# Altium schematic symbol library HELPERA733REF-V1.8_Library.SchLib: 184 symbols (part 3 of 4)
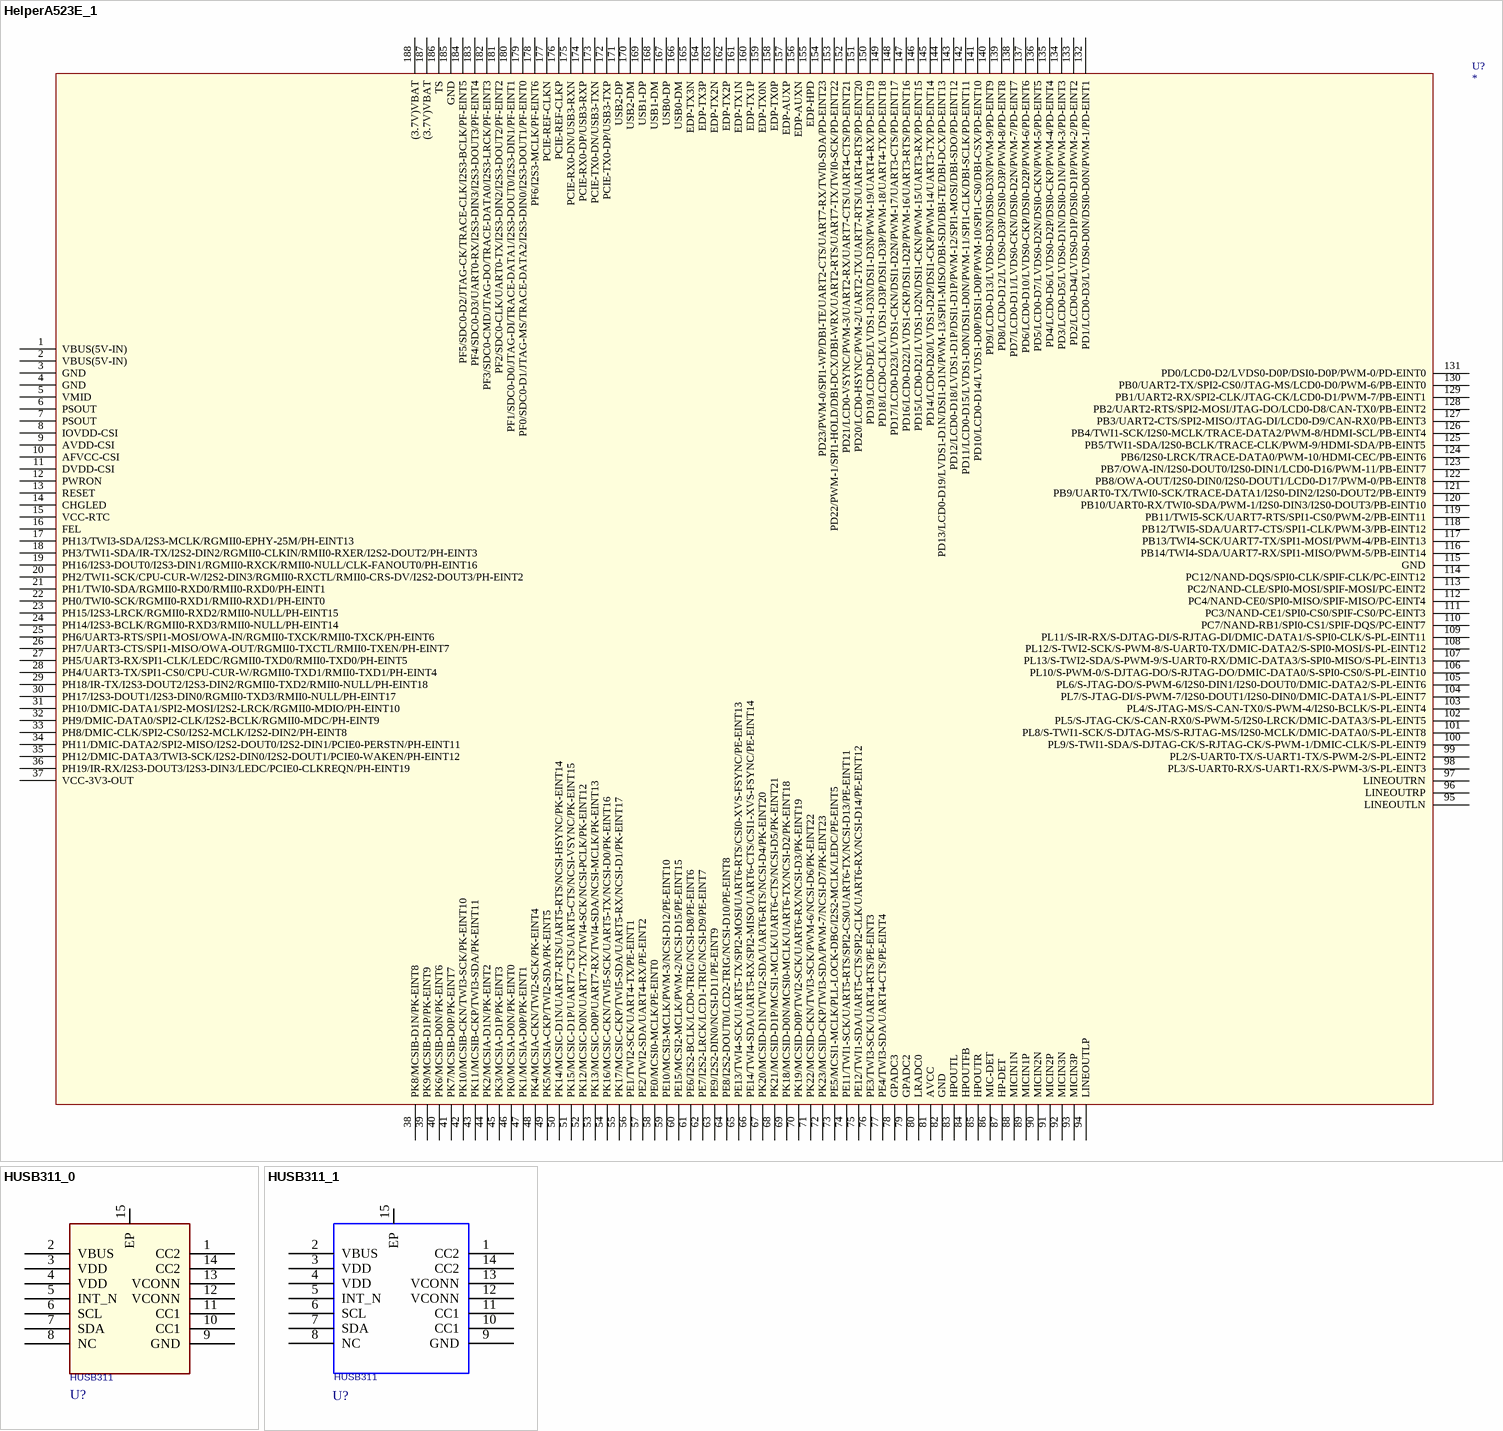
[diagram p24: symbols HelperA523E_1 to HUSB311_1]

## HelperA523E_1
designator U?
pins: 1 VBUS(5V-IN), 2 VBUS(5V-IN), 3 GND, 4 GND, 5 VMID, 6 PSOUT, 7 PSOUT, 8 IOVDD-CSI, 9 AVDD-CSI, 10 AFVCC-CSI, 11 DVDD-CSI, 12 PWRON, 13 RESET, 14 CHGLED, 15 VCC-RTC, 16 FEL, 17 PH13/TWI3-SDA/I2S3-MCLK/RGMII0-EPHY-25M/PH-EINT13, 18 PH3/TWI1-SDA/IR-TX/I2S2-DIN2/RGMII0-CLKIN/RMII0-RXER/I2S2-DOUT2/PH-EINT3, 19 PH16/I2S3-DOUT0/I2S3-DIN1/RGMII0-RXCK/RMII0-NULL/CLK-FANOUT0/PH-EINT16, 20 PH2/TWI1-SCK/CPU-CUR-W/I2S2-DIN3/RGMII0-RXCTL/RMII0-CRS-DV/I2S2-DOUT3/PH-EINT2, 21 PH1/TWI0-SDA/RGMII0-RXD0/RMII0-RXD0/PH-EINT1, 22 PH0/TWI0-SCK/RGMII0-RXD1/RMII0-RXD1/PH-EINT0, 23 PH15/I2S3-LRCK/RGMII0-RXD2/RMII0-NULL/PH-EINT15, 24 PH14/I2S3-BCLK/RGMII0-RXD3/RMII0-NULL/PH-EINT14, 25 PH6/UART3-RTS/SPI1-MOSI/OWA-IN/RGMII0-TXCK/RMII0-TXCK/PH-EINT6, 26 PH7/UART3-CTS/SPI1-MISO/OWA-OUT/RGMII0-TXCTL/RMII0-TXEN/PH-EINT7, 27 PH5/UART3-RX/SPI1-CLK/LEDC/RGMII0-TXD0/RMII0-TXD0/PH-EINT5, 28 PH4/UART3-TX/SPI1-CS0/CPU-CUR-W/RGMII0-TXD1/RMII0-TXD1/PH-EINT4, 29 PH18/IR-TX/I2S3-DOUT2/I2S3-DIN2/RGMII0-TXD2/RMII0-NULL/PH-EINT18, 30 PH17/I2S3-DOUT1/I2S3-DIN0/RGMII0-TXD3/RMII0-NULL/PH-EINT17, 31 PH10/DMIC-DATA1/SPI2-MOSI/I2S2-LRCK/RGMII0-MDIO/PH-EINT10, 32 PH9/DMIC-DATA0/SPI2-CLK/I2S2-BCLK/RGMII0-MDC/PH-EINT9, 33 PH8/DMIC-CLK/SPI2-CS0/I2S2-MCLK/I2S2-DIN2/PH-EINT8, 34 PH11/DMIC-DATA2/SPI2-MISO/I2S2-DOUT0/I2S2-DIN1/PCIE0-PERSTN/PH-EINT11, 35 PH12/DMIC-DATA3/TWI3-SCK/I2S2-DIN0/I2S2-DOUT1/PCIE0-WAKEN/PH-EINT12, 36 PH19/IR-RX/I2S3-DOUT3/I2S3-DIN3/LEDC/PCIE0-CLKREQN/PH-EINT19, 37 VCC-3V3-OUT, 38 PK8/MCSIB-D1N/PK-EINT8, 39 PK9/MCSIB-D1P/PK-EINT9, 40 PK6/MCSIB-D0N/PK-EINT6, 41 PK7/MCSIB-D0P/PK-EINT7, 42 PK10/MCSIB-CKN/TWI3-SCK/PK-EINT10, 43 PK11/MCSIB-CKP/TWI3-SDA/PK-EINT11, 44 PK2/MCSIA-D1N/PK-EINT2, 45 PK3/MCSIA-D1P/PK-EINT3, 46 PK0/MCSIA-D0N/PK-EINT0, 47 PK1/MCSIA-D0P/PK-EINT1, 48 PK4/MCSIA-CKN/TWI2-SCK/PK-EINT4, 49 PK5/MCSIA-CKP/TWI2-SDA/PK-EINT5, 50 PK14/MCSIC-D1N/UART7-RTS/UART5-RTS/NCSI-HSYNC/PK-EINT14, 51 PK15/MCSIC-D1P/UART7-CTS/UART5-CTS/NCSI-VSYNC/PK-EINT15, 52 PK12/MCSIC-D0N/UART7-TX/TWI4-SCK/NCSI-PCLK/PK-EINT12, 53 PK13/MCSIC-D0P/UART7-RX/TWI4-SDA/NCSI-MCLK/PK-EINT13, 54 PK16/MCSIC-CKN/TWI5-SCK/UART5-TX/NCSI-D0/PK-EINT16, 55 PK17/MCSIC-CKP/TWI5-SDA/UART5-RX/NCSI-D1/PK-EINT17, 56 PE1/TWI2-SCK/UART4-TX/PE-EINT1, 57 PE2/TWI2-SDA/UART4-RX/PE-EINT2, 58 PE0/MCSI0-MCLK/PE-EINT0, 59 PE10/MCSI3-MCLK/PWM-3/NCSI-D12/PE-EINT10, 60 PE15/MCSI2-MCLK/PWM-2/NCSI-D15/PE-EINT15, 61 PE6/I2S2-BCLK/LCD0-TRIG/NCSI-D8/PE-EINT6, 62 PE7/I2S2-LRCK/LCD1-TRIG/NCSI-D9/PE-EINT7, 63 PE9/I2S2-DIN0/NCSI-D11/PE-EINT9, 64 PE8/I2S2-DOUT0/LCD2-TRIG/NCSI-D10/PE-EINT8, 65 PE13/TWI4-SCK/UART5-TX/SPI2-MOSI/UART6-RTS/CSI0-XVS-FSYNC/PE-EINT13, 66 PE14/TWI4-SDA/UART5-RX/SPI2-MISO/UART6-CTS/CSI1-XVS-FSYNC/PE-EINT14, 67 PK20/MCSID-D1N/TWI2-SDA/UART6-RTS/NCSI-D4/PK-EINT20, 68 PK21/MCSID-D1P/MCSI1-MCLK/UART6-CTS/NCSI-D5/PK-EINT21, 69 PK18/MCSID-D0N/MCSI0-MCLK/UART6-TX/NCSI-D2/PK-EINT18, 70 PK19/MCSID-D0P/TWI2-SCK/UART6-RX/NCSI-D3/PK-EINT19, 71 PK22/MCSID-CKN/TWI3-SCK/PWM-6/NCSI-D6/PK-EINT22, 72 PK23/MCSID-CKP/TWI3-SDA/PWM-7/NCSI-D7/PK-EINT23, 73 PE5/MCSI1-MCLK/PLL-LOCK-DBG/I2S2-MCLK/LEDC/PE-EINT5, 74 PE11/TWI1-SCK/UART5-RTS/SPI2-CS0/UART6-TX/NCSI-D13/PE-EINT11, 75 PE12/TWI1-SDA/UART5-CTS/SPI2-CLK/UART6-RX/NCSI-D14/PE-EINT12, 76 PE3/TWI3-SCK/UART4-RTS/PE-EINT3, 77 PE4/TWI3-SDA/UART4-CTS/PE-EINT4, 78 GPADC3, 79 GPADC2, 80 LRADC0, 81 AVCC, 82 GND, 83 HPOUTL, 84 HPOUTFB, 85 HPOUTR, 86 MIC-DET, 87 HP-DET, 88 MICIN1N, 89 MICIN1P, 90 MICIN2N, 91 MICIN2P, 92 MICIN3N, 93 MICIN3P, 94 LINEOUTLP, 95 LINEOUTLN, 96 LINEOUTRP, 97 LINEOUTRN, 98 PL3/S-UART0-RX/S-UART1-RX/S-PWM-3/S-PL-EINT3, 99 PL2/S-UART0-TX/S-UART1-TX/S-PWM-2/S-PL-EINT2, 100 PL9/S-TWI1-SDA/S-DJTAG-CK/S-RJTAG-CK/S-PWM-1/DMIC-CLK/S-PL-EINT9, 101 PL8/S-TWI1-SCK/S-DJTAG-MS/S-RJTAG-MS/I2S0-MCLK/DMIC-DATA0/S-PL-EINT8, 102 PL5/S-JTAG-CK/S-CAN-RX0/S-PWM-5/I2S0-LRCK/DMIC-DATA3/S-PL-EINT5, 103 PL4/S-JTAG-MS/S-CAN-TX0/S-PWM-4/I2S0-BCLK/S-PL-EINT4, 104 PL7/S-JTAG-DI/S-PWM-7/I2S0-DOUT1/I2S0-DIN0/DMIC-DATA1/S-PL-EINT7, 105 PL6/S-JTAG-DO/S-PWM-6/I2S0-DIN1/I2S0-DOUT0/DMIC-DATA2/S-PL-EINT6, 106 PL10/S-PWM-0/S-DJTAG-DO/S-RJTAG-DO/DMIC-DATA0/S-SPI0-CS0/S-PL-EINT10, 107 PL13/S-TWI2-SDA/S-PWM-9/S-UART0-RX/DMIC-DATA3/S-SPI0-MISO/S-PL-EINT13, 108 PL12/S-TWI2-SCK/S-PWM-8/S-UART0-TX/DMIC-DATA2/S-SPI0-MOSI/S-PL-EINT12, 109 PL11/S-IR-RX/S-DJTAG-DI/S-RJTAG-DI/DMIC-DATA1/S-SPI0-CLK/S-PL-EINT11, 110 PC7/NAND-RB1/SPI0-CS1/SPIF-DQS/PC-EINT7, 111 PC3/NAND-CE1/SPI0-CS0/SPIF-CS0/PC-EINT3, 112 PC4/NAND-CE0/SPI0-MISO/SPIF-MISO/PC-EINT4, 113 PC2/NAND-CLE/SPI0-MOSI/SPIF-MOSI/PC-EINT2, 114 PC12/NAND-DQS/SPI0-CLK/SPIF-CLK/PC-EINT12, 115 GND, 116 PB14/TWI4-SDA/UART7-RX/SPI1-MISO/PWM-5/PB-EINT14, 117 PB13/TWI4-SCK/UART7-TX/SPI1-MOSI/PWM-4/PB-EINT13, 118 PB12/TWI5-SDA/UART7-CTS/SPI1-CLK/PWM-3/PB-EINT12, 119 PB11/TWI5-SCK/UART7-RTS/SPI1-CS0/PWM-2/PB-EINT11, 120 PB10/UART0-RX/TWI0-SDA/PWM-1/I2S0-DIN3/I2S0-DOUT3/PB-EINT10, 121 PB9/UART0-TX/TWI0-SCK/TRACE-DATA1/I2S0-DIN2/I2S0-DOUT2/PB-EINT9, 122 PB8/OWA-OUT/I2S0-DIN0/I2S0-DOUT1/LCD0-D17/PWM-0/PB-EINT8, 123 PB7/OWA-IN/I2S0-DOUT0/I2S0-DIN1/LCD0-D16/PWM-11/PB-EINT7, 124 PB6/I2S0-LRCK/TRACE-DATA0/PWM-10/HDMI-CEC/PB-EINT6, 125 PB5/TWI1-SDA/I2S0-BCLK/TRACE-CLK/PWM-9/HDMI-SDA/PB-EINT5, 126 PB4/TWI1-SCK/I2S0-MCLK/TRACE-DATA2/PWM-8/HDMI-SCL/PB-EINT4, 127 PB3/UART2-CTS/SPI2-MISO/JTAG-DI/LCD0-D9/CAN-RX0/PB-EINT3, 128 PB2/UART2-RTS/SPI2-MOSI/JTAG-DO/LCD0-D8/CAN-TX0/PB-EINT2, 129 PB1/UART2-RX/SPI2-CLK/JTAG-CK/LCD0-D1/PWM-7/PB-EINT1, 130 PB0/UART2-TX/SPI2-CS0/JTAG-MS/LCD0-D0/PWM-6/PB-EINT0, 131 PD0/LCD0-D2/LVDS0-D0P/DSI0-D0P/PWM-0/PD-EINT0, 132 PD1/LCD0-D3/LVDS0-D0N/DSI0-D0N/PWM-1/PD-EINT1, 133 PD2/LCD0-D4/LVDS0-D1P/DSI0-D1P/PWM-2/PD-EINT2, 134 PD3/LCD0-D5/LVDS0-D1N/DSI0-D1N/PWM-3/PD-EINT3, 135 PD4/LCD0-D6/LVDS0-D2P/DSI0-CKP/PWM-4/PD-EINT4, 136 PD5/LCD0-D7/LVDS0-D2N/DSI0-CKN/PWM-5/PD-EINT5, 137 PD6/LCD0-D10/LVDS0-CKP/DSI0-D2P/PWM-6/PD-EINT6, 138 PD7/LCD0-D11/LVDS0-CKN/DSI0-D2N/PWM-7/PD-EINT7, 139 PD8/LCD0-D12/LVDS0-D3P/DSI0-D3P/PWM-8/PD-EINT8, 140 PD9/LCD0-D13/LVDS0-D3N/DSI0-D3N/PWM-9/PD-EINT9, 141 PD10/LCD0-D14/LVDS1-D0P/DSI1-D0P/PWM-10/SPI1-CS0/DBI-CSX/PD-EINT10, 142 PD11/LCD0-D15/LVDS1-D0N/DSI1-D0N/PWM-11/SPI1-CLK/DBI-SCLK/PD-EINT11, 143 PD12/LCD0-D18/LVDS1-D1P/DSI1-D1P/PWM-12/SPI1-MOSI/DBI-SDO/PD-EINT12, 144 PD13/LCD0-D19/LVDS1-D1N/DSI1-D1N/PWM-13/SPI1-MISO/DBI-SDI/DBI-TE/DBI-DCX/PD-EINT13, 145 PD14/LCD0-D20/LVDS1-D2P/DSI1-CKP/PWM-14/UART3-TX/PD-EINT14, 146 PD15/LCD0-D21/LVDS1-D2N/DSI1-CKN/PWM-15/UART3-RX/PD-EINT15, 147 PD16/LCD0-D22/LVDS1-CKP/DSI1-D2P/PWM-16/UART3-RTS/PD-EINT16, 148 PD17/LCD0-D23/LVDS1-CKN/DSI1-D2N/PWM-17/UART3-CTS/PD-EINT17, 149 PD18/LCD0-CLK/LVDS1-D3P/DSI1-D3P/PWM-18/UART4-TX/PD-EINT18, 150 PD19/LCD0-DE/LVDS1-D3N/DSI1-D3N/PWM-19/UART4-RX/PD-EINT19, 151 PD20/LCD0-HSYNC/PWM-2/UART2-TX/UART7-RTS/UART4-RTS/PD-EINT20, 152 PD21/LCD0-VSYNC/PWM-3/UART2-RX/UART7-CTS/UART4-CTS/PD-EINT21, 153 PD22/PWM-1/SPI1-HOLD/DBI-DCX/DBI-WRX/UART2-RTS/UART7-TX/TWI0-SCK/PD-EINT22, 154 PD23/PWM-0/SPI1-WP/DBI-TE/UART2-CTS/UART7-RX/TWI0-SDA/PD-EINT23, 155 EDP-HPD, 156 EDP-AUXN, 157 EDP-AUXP, 158 EDP-TX0P, 159 EDP-TX0N, 160 EDP-TX1P, 161 EDP-TX1N, 162 EDP-TX2P, 163 EDP-TX2N, 164 EDP-TX3P, 165 EDP-TX3N, 166 USB0-DM, 167 USB0-DP, 168 USB1-DM, 169 USB1-DP, 170 USB2-DM, 171 USB2-DP, 172 PCIE-TX0-DP/USB3-TXP, 173 PCIE-TX0-DN/USB3-TXN, 174 PCIE-RX0-DP/USB3-RXP, 175 PCIE-RX0-DN/USB3-RXN, 176 PCIE-REF-CLKP, 177 PCIE-REF-CLKN, 178 PF6/I2S3-MCLK/PF-EINT6, 179 PF0/SDC0-D1/JTAG-MS/TRACE-DATA2/I2S3-DIN0/I2S3-DOUT1/PF-EINT0, 180 PF1/SDC0-D0/JTAG-DI/TRACE-DATA1/I2S3-DOUT0/I2S3-DIN1/PF-EINT1, 181 PF2/SDC0-CLK/UART0-TX/I2S3-DIN2/I2S3-DOUT2/PF-EINT2, 182 PF3/SDC0-CMD/JTAG-DO/TRACE-DATA0/I2S3-LRCK/PF-EINT3, 183 PF4/SDC0-D3/UART0-RX/I2S3-DIN3/I2S3-DOUT3/PF-EINT4, 184 PF5/SDC0-D2/JTAG-CK/TRACE-CLK/I2S3-BCLK/PF-EINT5, 185 GND, 186 TS, 187 (3.7V)VBAT, 188 (3.7V)VBAT

## HUSB311_0
designator U?, comment HUSB311
footprint HUSB311
pins: 1 CC2, 2 VBUS, 3 VDD, 4 VDD, 5 INT_N, 6 SCL, 7 SDA, 8 NC, 9 GND, 10 CC1, 11 CC1, 12 VCONN, 13 VCONN, 14 CC2, 15 EP

## HUSB311_1
designator U?, comment HUSB311
footprint HUSB311
pins: 1 CC2, 2 VBUS, 3 VDD, 4 VDD, 5 INT_N, 6 SCL, 7 SDA, 8 NC, 9 GND, 10 CC1, 11 CC1, 12 VCONN, 13 VCONN, 14 CC2, 15 EP

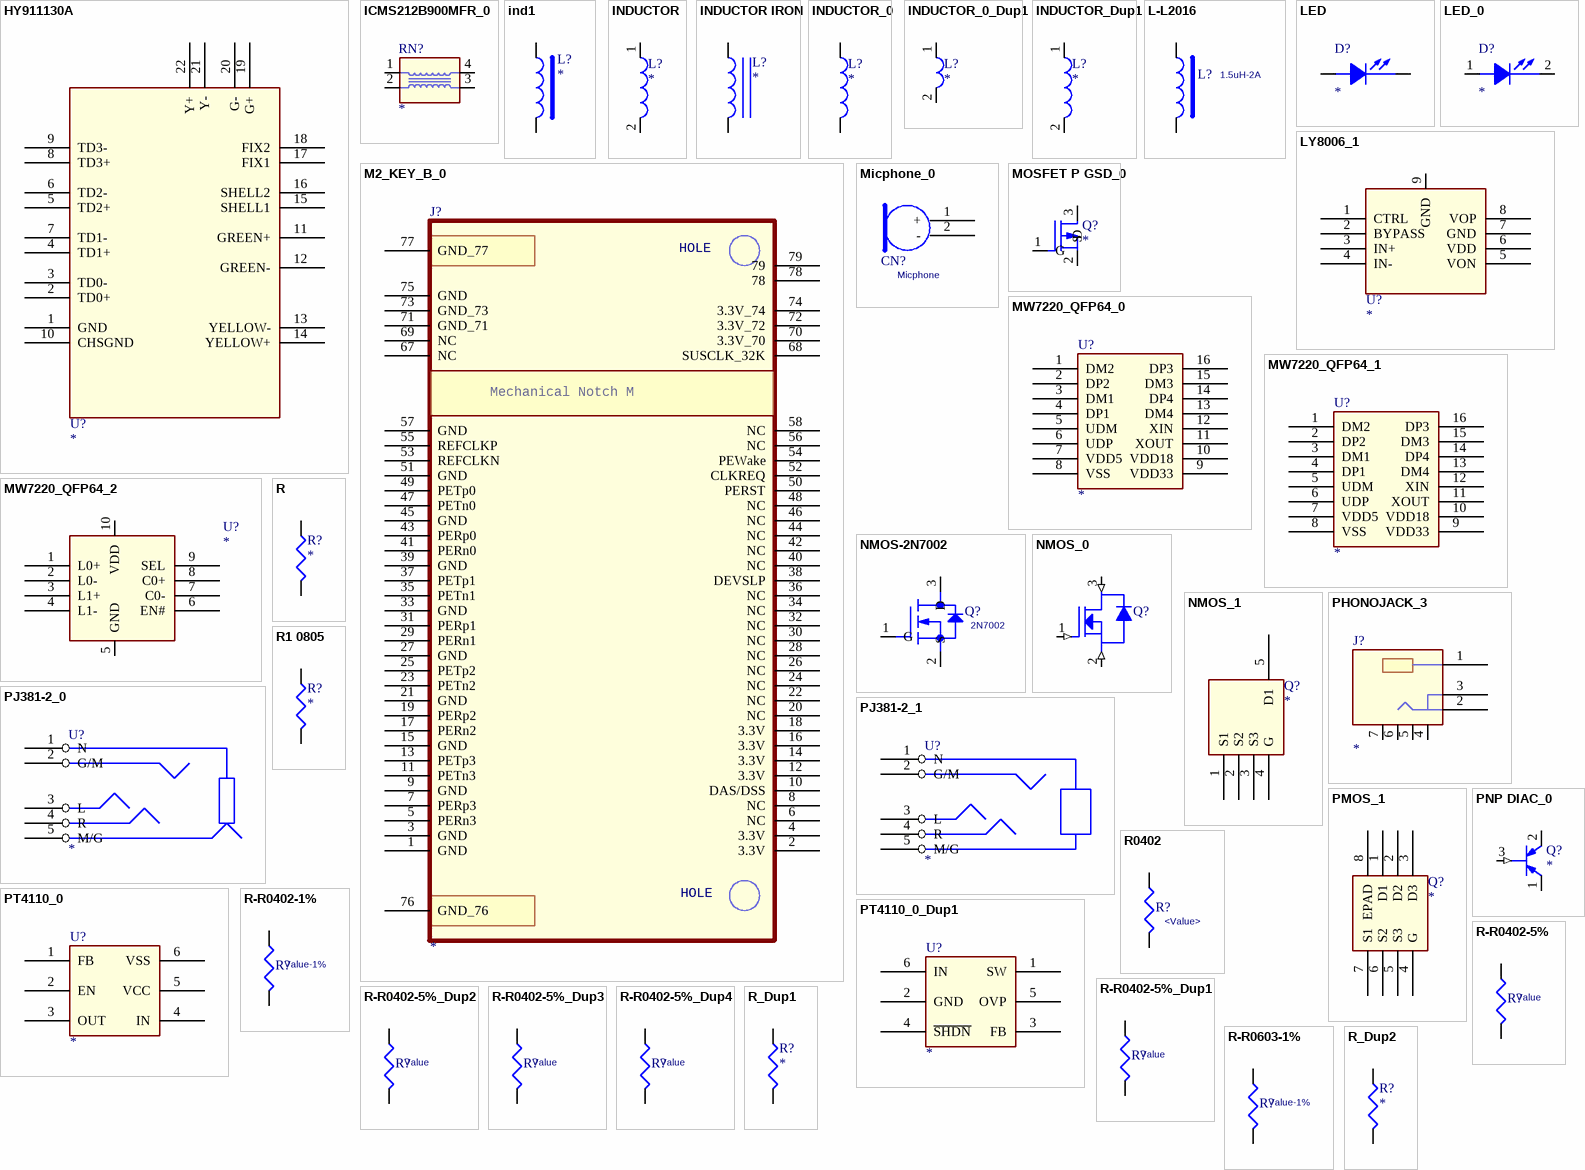
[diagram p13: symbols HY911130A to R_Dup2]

## HY911130A
designator U?
pins: 1 GND, 2 TD0+, 3 TD0-, 4 TD1+, 5 TD2+, 6 TD2-, 7 TD1-, 8 TD3+, 9 TD3-, 10 CHSGND, 11 GREEN+, 12 GREEN-, 13 YELLOW-, 14 YELLOW+, 15 SHELL1, 16 SHELL2, 17 FIX1, 18 FIX2, 19 G+, 20 G-, 21 Y-, 22 Y+

## ICMS212B900MFR_0
designator RN?
footprint ICMS212B900MFR
pins: 1, 2, 3, 4

## ind1
designator L?
pins: 1, 2

## INDUCTOR
designator L?
pins: 1, 2

## INDUCTOR IRON
designator L?
pins: 1, 2

## INDUCTOR_0
designator L?
pins: 1, 2

## INDUCTOR_0_Dup1
designator L?
OriginalSymbolOrigin: (10,0)
pins: 1, 2

## INDUCTOR_Dup1
designator L?
pins: 1, 2

## L-L2016
designator L?, comment 1.5uH-2A
Parameter: L2016
footprint LP160_200H100
pins: 1, 2

## LED
designator D?
pins: 1 ANODE, 2 CATHODE

## LED_0
designator D?
pins: 1 ANODE, 2 CATHODE

## LY8006_1
designator U?
pins: 1 CTRL, 2 BYPASS, 3 IN+, 4 IN-, 5 VON, 6 VDD, 7 GND, 8 VOP, 9 GND

## M2_KEY_B_0
designator J?
footprint M2_KEY_B_M
pins: 1 GND, 2 3.3V, 3 GND, 4 3.3V, 5 PERn3, 6 NC, 7 PERp3, 8 NC, 9 GND, 10 DAS/DSS, 11 PETn3, 12 3.3V, 13 PETp3, 14 3.3V, 15 GND, 16 3.3V, 17 PERn2, 18 3.3V, 19 PERp2, 20 NC, 21 GND, 22 NC, 23 PETn2, 24 NC, 25 PETp2, 26 NC, 27 GND, 28 NC, 29 PERn1, 30 NC, 31 PERp1, 32 NC, 33 GND, 34 NC, 35 PETn1, 36 NC, 37 PETp1, 38 DEVSLP, 39 GND, 40 NC, 41 PERn0, 42 NC, 43 PERp0, 44 NC, 45 GND, 46 NC, 47 PETn0, 48 NC, 49 PETp0, 50 PERST, 51 GND, 52 CLKREQ, 53 REFCLKN, 54 PEWake, 55 REFCLKP, 56 NC, 57 GND, 58 NC, 67 NC, 68 SUSCLK_32K, 69 NC, 70 3.3V_70, 71 GND_71, 72 3.3V_72, 73 GND_73, 74 3.3V_74, 75 GND, 76 GND_76, 77 GND_77, 78, 79

## Micphone_0
designator CN?, comment Micphone
footprint Micphone Connector
pins: 1 +, 2 -

## MOSFET P GSD_0
designator Q?
pins: 1 G, 2 S, 3 D

## MW7220_QFP64_0
designator U?
pins: 1 DM2, 2 DP2, 3 DM1, 4 DP1, 5 UDM, 6 UDP, 7 VDD5 (power), 8 VSS (power), 9 VDD33 (power), 10 VDD18 (power), 11 XOUT, 12 XIN, 13 DM4, 14 DP4, 15 DM3, 16 DP3

## MW7220_QFP64_1
designator U?
pins: 1 DM2, 2 DP2, 3 DM1, 4 DP1, 5 UDM, 6 UDP, 7 VDD5, 8 VSS (power), 9 VDD33 (power), 10 VDD18 (power), 11 XOUT, 12 XIN, 13 DM4, 14 DP4, 15 DM3, 16 DP3

## MW7220_QFP64_2
designator U?
pins: 1 L0+, 2 L0-, 3 L1+, 4 L1-, 5 GND, 6 EN#, 7 C0-, 8 C0+ (power), 9 SEL (power), 10 VDD (power)

## NMOS-2N7002
designator Q?, comment 2N7002
ID: MOS0002; Parameter: SOT23
footprint SOT3P95B130_290H103
pins: 1 G, 2 S, 3 D

## NMOS_0
designator Q?, comment xp151  (value not drawn)
footprint sot-23
pins: 1 GATE (in), 2 SOURCE (in), 3 DRAIN (in)

## NMOS_1
designator Q?
pins: 1 S1, 2 S2, 3 S3, 4 G, 5 D1

## PHONOJACK_3
designator J?
footprint TSH-3865D
pins: 1, 2, 3, 4, 5, 6, 7

## PJ381-2_0
designator U?
footprint PJ381-2
pins: 1 N, 2 G/M, 3 L, 4 R, 5 M/G

## PJ381-2_1
designator U?
footprint PJ381-2
pins: 1 N, 2 G/M, 3 L, 4 R, 5 M/G

## PMOS_1
designator Q?
pins: 1 D1, 2 D2, 3 D3, 4 G, 5 S3, 6 S2, 7 S1, 8 EPAD

## PNP DIAC_0
designator Q?
pins: 1 COLLECTOR, 2 EMITTER, 3 BASE (in)

## PT4110_0
designator U?
footprint SOT89-5
pins: 1 FB, 2 EN, 3 OUT, 4 IN, 5 VCC, 6 VSS

## PT4110_0_Dup1
designator U?
footprint SOT89-5
pins: 1 SW, 2 GND, 3 FB, 4 ~{SHDN}, 5 OVP, 6 IN

## R
designator R?
pins: 1, 2

## R1 0805
designator R?
footprint 0805
pins: 1, 2

## R0402
designator R?, comment <Value>
footprint R0402
pins: 1, 2

## R-R0402-1%
designator R?, comment Value-1%
footprint R0402
pins: 1, 2

## R-R0402-5%
designator R?, comment Value
footprint R0402
pins: 1, 2

## R-R0402-5%_Dup1
designator R?, comment Value
footprint R0402
pins: 1, 2

## R-R0402-5%_Dup2
designator R?, comment Value
footprint R0402
pins: 1, 2

## R-R0402-5%_Dup3
designator R?, comment Value
footprint R0402
pins: 1, 2

## R-R0402-5%_Dup4
designator R?, comment Value
footprint R0402
pins: 1, 2

## R-R0603-1%
designator R?, comment Value-1%
footprint R0603
pins: 1, 2

## R_Dup1
designator R?
pins: 1, 2

## R_Dup2
designator R?
pins: 1, 2

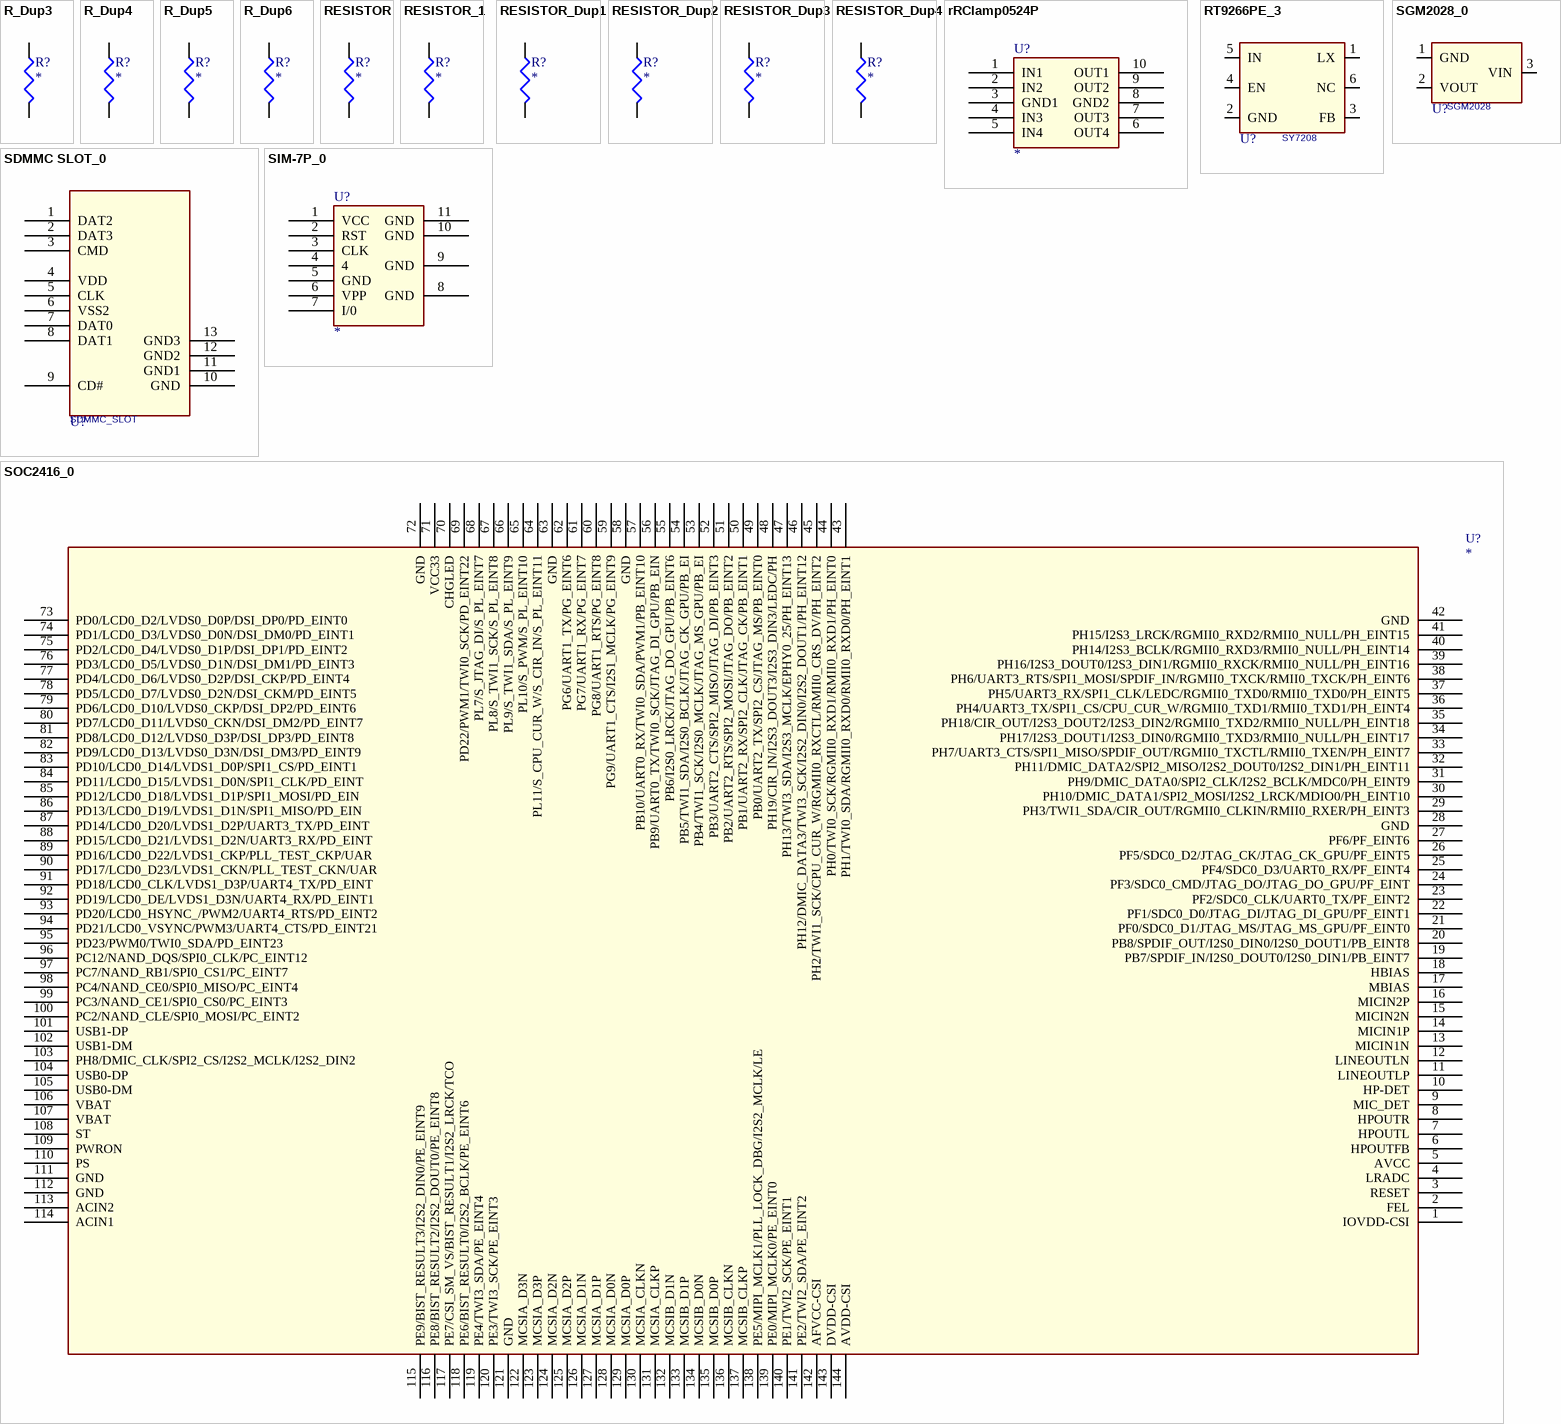
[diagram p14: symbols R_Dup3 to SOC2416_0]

## R_Dup3
designator R?
pins: 1, 2

## R_Dup4
designator R?
pins: 1, 2

## R_Dup5
designator R?
pins: 1, 2

## R_Dup6
designator R?
pins: 1, 2

## RESISTOR
designator R?
pins: 1, 2

## RESISTOR_1
designator R?
pins: 1, 2

## RESISTOR_Dup1
designator R?
pins: 1, 2

## RESISTOR_Dup2
designator R?
pins: 1, 2

## RESISTOR_Dup3
designator R?
pins: 1, 2

## RESISTOR_Dup4
designator R?
pins: 1, 2

## rRClamp0524P
designator U?
pins: 1 IN1, 2 IN2, 3 GND1, 4 IN3, 5 IN4, 6 OUT4, 7 OUT3, 8 GND2, 9 OUT2, 10 OUT1

## RT9266PE_3
designator U?, comment SY7208
footprint SOT23-6
pins: 1 LX, 2 GND, 3 FB, 4 EN, 5 IN, 6 NC

## SDMMC SLOT_0
designator U?, comment SDMMC_SLOT
pins: 1 DAT2, 2 DAT3, 3 CMD, 4 VDD, 5 CLK, 6 VSS2, 7 DAT0, 8 DAT1, 9 CD#, 10 GND (power), 11 GND1, 12 GND2, 13 GND3

## SGM2028_0
designator U?, comment SGM2028
ID: U-IC0031; Parameter: SOT23-5,input 2.5~5.5V,current=0.5A
footprint SOT5P95B160_300H130
pins: 1 GND, 2 VOUT, 3 VIN

## SIM-7P_0
designator U?
pins: 1 VCC, 2 RST, 3 CLK, 4, 5 GND, 6 VPP, 7 I/0, 8 GND, 9 GND, 10 GND, 11 GND

## SOC2416_0
designator U?
footprint SOC4X4_1MM
pins: 1 IOVDD-CSI, 2 FEL, 3 RESET, 4 LRADC, 5 AVCC, 6 HPOUTFB, 7 HPOUTL, 8 HPOUTR, 9 MIC_DET, 10 HP-DET, 11 LINEOUTLP, 12 LINEOUTLN, 13 MICIN1N, 14 MICIN1P, 15 MICIN2N, 16 MICIN2P, 17 MBIAS, 18 HBIAS, 19 PB7/SPDIF_IN/I2S0_DOUT0/I2S0_DIN1/PB_EINT7, 20 PB8/SPDIF_OUT/I2S0_DIN0/I2S0_DOUT1/PB_EINT8, 21 PF0/SDC0_D1/JTAG_MS/JTAG_MS_GPU/PF_EINT0, 22 PF1/SDC0_D0/JTAG_DI/JTAG_DI_GPU/PF_EINT1, 23 PF2/SDC0_CLK/UART0_TX/PF_EINT2, 24 PF3/SDC0_CMD/JTAG_DO/JTAG_DO_GPU/PF_EINT, 25 PF4/SDC0_D3/UART0_RX/PF_EINT4, 26 PF5/SDC0_D2/JTAG_CK/JTAG_CK_GPU/PF_EINT5, 27 PF6/PF_EINT6, 28 GND, 29 PH3/TWI1_SDA/CIR_OUT/RGMII0_CLKIN/RMII0_RXER/PH_EINT3, 30 PH10/DMIC_DATA1/SPI2_MOSI/I2S2_LRCK/MDIO0/PH_EINT10, 31 PH9/DMIC_DATA0/SPI2_CLK/I2S2_BCLK/MDC0/PH_EINT9, 32 PH11/DMIC_DATA2/SPI2_MISO/I2S2_DOUT0/I2S2_DIN1/PH_EINT11, 33 PH7/UART3_CTS/SPI1_MISO/SPDIF_OUT/RGMII0_TXCTL/RMII0_TXEN/PH_EINT7, 34 PH17/I2S3_DOUT1/I2S3_DIN0/RGMII0_TXD3/RMII0_NULL/PH_EINT17, 35 PH18/CIR_OUT/I2S3_DOUT2/I2S3_DIN2/RGMII0_TXD2/RMII0_NULL/PH_EINT18, 36 PH4/UART3_TX/SPI1_CS/CPU_CUR_W/RGMII0_TXD1/RMII0_TXD1/PH_EINT4, 37 PH5/UART3_RX/SPI1_CLK/LEDC/RGMII0_TXD0/RMII0_TXD0/PH_EINT5, 38 PH6/UART3_RTS/SPI1_MOSI/SPDIF_IN/RGMII0_TXCK/RMII0_TXCK/PH_EINT6, 39 PH16/I2S3_DOUT0/I2S3_DIN1/RGMII0_RXCK/RMII0_NULL/PH_EINT16, 40 PH14/I2S3_BCLK/RGMII0_RXD3/RMII0_NULL/PH_EINT14, 41 PH15/I2S3_LRCK/RGMII0_RXD2/RMII0_NULL/PH_EINT15, 42 GND, 43 PH1/TWI0_SDA/RGMII0_RXD0/RMII0_RXD0/PH_EINT1, 44 PH0/TWI0_SCK/RGMII0_RXD1/RMII0_RXD1/PH_EINT0, 45 PH2/TWI1_SCK/CPU_CUR_W/RGMII0_RXCTL/RMII0_CRS_DV/PH_EINT2, 46 PH12/DMIC_DATA3/TWI3_SCK/I2S2_DIN0/I2S2_DOUT1/PH_EINT12, 47 PH13/TWI3_SDA/I2S3_MCLK/EPHY0_25/PH_EINT13, 48 PH19/CIR_IN/I2S3_DOUT3/I2S3_DIN3/LEDC/PH, 49 PB0/UART2_TX/SPI2_CS/JTAG_MS/PB_EINT0, 50 PB1/UART2_RX/SPI2_CLK/JTAG_CK/PB_EINT1, 51 PB2/UART2_RTS/SPI2_MOSI/JTAG_DO/PB_EINT2, 52 PB3/UART2_CTS/SPI2_MISO/JTAG_DI/PB_EINT3, 53 PB4/TWI1_SCK/I2S0_MCLK/JTAG_MS_GPU/PB_EI, 54 PB5/TWI1_SDA/I2S0_BCLK/JTAG_CK_GPU/PB_EI, 55 PB6/I2S0_LRCK/JTAG_DO_GPU/PB_EINT6, 56 PB9/UART0_TX/TWI0_SCK/JTAG_DI_GPU/PB_EIN, 57 PB10/UART0_RX/TWI0_SDA/PWM1/PB_EINT10 (power), 58 GND, 59 PG9/UART1_CTS/I2S1_MCLK/PG_EINT9, 60 PG8/UART1_RTS/PG_EINT8, 61 PG7/UART1_RX/PG_EINT7, 62 PG6/UART1_TX/PG_EINT6, 63 GND, 64 PL11/S_CPU_CUR_W/S_CIR_IN/S_PL_EINT11, 65 PL10/S_PWM/S_PL_EINT10, 66 PL9/S_TWI1_SDA/S_PL_EINT9, 67 PL8/S_TWI1_SCK/S_PL_EINT8, 68 PL7/S_JTAG_DI/S_PL_EINT7, 69 PD22/PWM1/TWI0_SCK/PD_EINT22, 70 CHGLED, 71 VCC33, 72 GND, 73 PD0/LCD0_D2/LVDS0_D0P/DSI_DP0/PD_EINT0, 74 PD1/LCD0_D3/LVDS0_D0N/DSI_DM0/PD_EINT1, 75 PD2/LCD0_D4/LVDS0_D1P/DSI_DP1/PD_EINT2, 76 PD3/LCD0_D5/LVDS0_D1N/DSI_DM1/PD_EINT3, 77 PD4/LCD0_D6/LVDS0_D2P/DSI_CKP/PD_EINT4, 78 PD5/LCD0_D7/LVDS0_D2N/DSI_CKM/PD_EINT5, 79 PD6/LCD0_D10/LVDS0_CKP/DSI_DP2/PD_EINT6, 80 PD7/LCD0_D11/LVDS0_CKN/DSI_DM2/PD_EINT7, 81 PD8/LCD0_D12/LVDS0_D3P/DSI_DP3/PD_EINT8, 82 PD9/LCD0_D13/LVDS0_D3N/DSI_DM3/PD_EINT9, 83 PD10/LCD0_D14/LVDS1_D0P/SPI1_CS/PD_EINT1, 84 PD11/LCD0_D15/LVDS1_D0N/SPI1_CLK/PD_EINT, 85 PD12/LCD0_D18/LVDS1_D1P/SPI1_MOSI/PD_EIN, 86 PD13/LCD0_D19/LVDS1_D1N/SPI1_MISO/PD_EIN, 87 PD14/LCD0_D20/LVDS1_D2P/UART3_TX/PD_EINT, 88 PD15/LCD0_D21/LVDS1_D2N/UART3_RX/PD_EINT (power), 89 PD16/LCD0_D22/LVDS1_CKP/PLL_TEST_CKP/UAR, 90 PD17/LCD0_D23/LVDS1_CKN/PLL_TEST_CKN/UAR, 91 PD18/LCD0_CLK/LVDS1_D3P/UART4_TX/PD_EINT, 92 PD19/LCD0_DE/LVDS1_D3N/UART4_RX/PD_EINT1, 93 PD20/LCD0_HSYNC_/PWM2/UART4_RTS/PD_EINT2, 94 PD21/LCD0_VSYNC/PWM3/UART4_CTS/PD_EINT21, 95 PD23/PWM0/TWI0_SDA/PD_EINT23, 96 PC12/NAND_DQS/SPI0_CLK/PC_EINT12 (power), 97 PC7/NAND_RB1/SPI0_CS1/PC_EINT7, 98 PC4/NAND_CE0/SPI0_MISO/PC_EINT4, 99 PC3/NAND_CE1/SPI0_CS0/PC_EINT3, 100 PC2/NAND_CLE/SPI0_MOSI/PC_EINT2, 101 USB1-DP, 102 USB1-DM, 103 PH8/DMIC_CLK/SPI2_CS/I2S2_MCLK/I2S2_DIN2, 104 USB0-DP, 105 USB0-DM, 106 VBAT, 107 VBAT, 108 ST, 109 PWRON, 110 PS, 111 GND, 112 GND, 113 ACIN2, 114 ACIN1, 115 PE9/BIST_RESULT3/I2S2_DIN0/PE_EINT9, 116 PE8/BIST_RESULT2/I2S2_DOUT0/PE_EINT8, 117 PE7/CSI_SM_VS/BIST_RESULT1/I2S2_LRCK/TCO, 118 PE6/BIST_RESULT0/I2S2_BCLK/PE_EINT6, 119 PE4/TWI3_SDA/PE_EINT4, 120 PE3/TWI3_SCK/PE_EINT3, 121 GND, 122 MCSIA_D3N, 123 MCSIA_D3P (power), 124 MCSIA_D2N, 125 MCSIA_D2P, 126 MCSIA_D1N, 127 MCSIA_D1P, 128 MCSIA_D0N (power), 129 MCSIA_D0P (power), 130 MCSIA_CLKN, 131 MCSIA_CLKP, 132 MCSIB_D1N, 133 MCSIB_D1P, 134 MCSIB_D0N, 135 MCSIB_D0P, 136 MCSIB_CLKN, 137 MCSIB_CLKP, 138 PE5/MIPI_MCLK1/PLL_LOCK_DBG/I2S2_MCLK/LE, 139 PE0/MIPI_MCLK0/PE_EINT0, 140 PE1/TWI2_SCK/PE_EINT1, 141 PE2/TWI2_SDA/PE_EINT2, 142 AFVCC-CSI, 143 DVDD-CSI, 144 AVDD-CSI

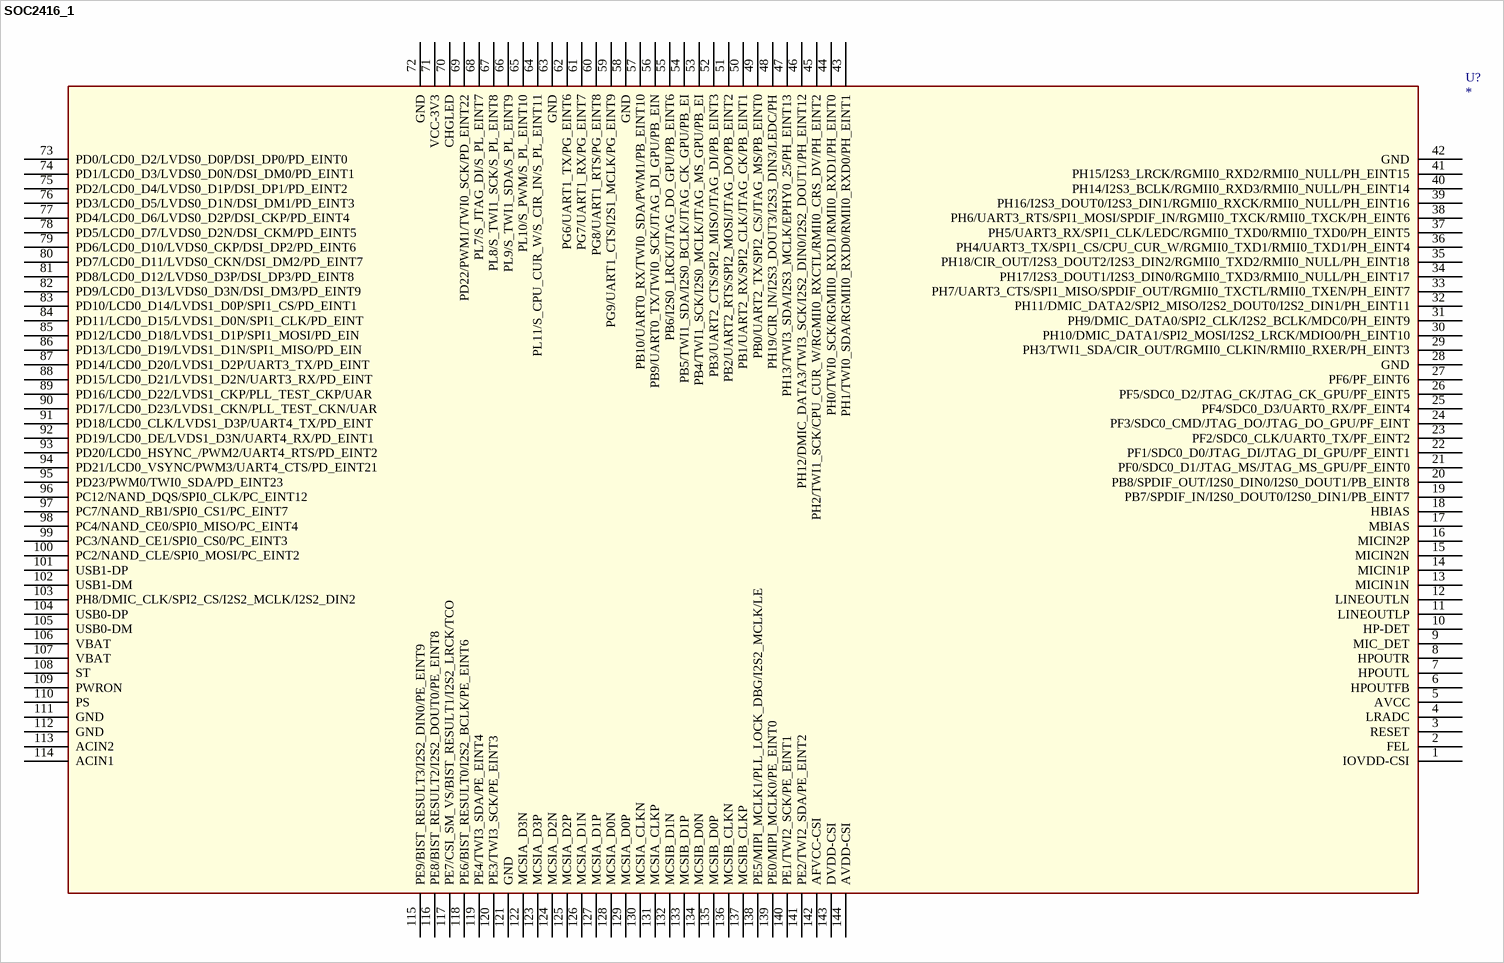
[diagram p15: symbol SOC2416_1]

## SOC2416_1
designator U?
footprint SOC4X4_1MM
pins: 1 IOVDD-CSI, 2 FEL, 3 RESET, 4 LRADC, 5 AVCC, 6 HPOUTFB, 7 HPOUTL, 8 HPOUTR, 9 MIC_DET, 10 HP-DET, 11 LINEOUTLP, 12 LINEOUTLN, 13 MICIN1N, 14 MICIN1P, 15 MICIN2N, 16 MICIN2P, 17 MBIAS, 18 HBIAS, 19 PB7/SPDIF_IN/I2S0_DOUT0/I2S0_DIN1/PB_EINT7, 20 PB8/SPDIF_OUT/I2S0_DIN0/I2S0_DOUT1/PB_EINT8, 21 PF0/SDC0_D1/JTAG_MS/JTAG_MS_GPU/PF_EINT0, 22 PF1/SDC0_D0/JTAG_DI/JTAG_DI_GPU/PF_EINT1, 23 PF2/SDC0_CLK/UART0_TX/PF_EINT2, 24 PF3/SDC0_CMD/JTAG_DO/JTAG_DO_GPU/PF_EINT, 25 PF4/SDC0_D3/UART0_RX/PF_EINT4, 26 PF5/SDC0_D2/JTAG_CK/JTAG_CK_GPU/PF_EINT5, 27 PF6/PF_EINT6, 28 GND, 29 PH3/TWI1_SDA/CIR_OUT/RGMII0_CLKIN/RMII0_RXER/PH_EINT3, 30 PH10/DMIC_DATA1/SPI2_MOSI/I2S2_LRCK/MDIO0/PH_EINT10, 31 PH9/DMIC_DATA0/SPI2_CLK/I2S2_BCLK/MDC0/PH_EINT9, 32 PH11/DMIC_DATA2/SPI2_MISO/I2S2_DOUT0/I2S2_DIN1/PH_EINT11, 33 PH7/UART3_CTS/SPI1_MISO/SPDIF_OUT/RGMII0_TXCTL/RMII0_TXEN/PH_EINT7, 34 PH17/I2S3_DOUT1/I2S3_DIN0/RGMII0_TXD3/RMII0_NULL/PH_EINT17, 35 PH18/CIR_OUT/I2S3_DOUT2/I2S3_DIN2/RGMII0_TXD2/RMII0_NULL/PH_EINT18, 36 PH4/UART3_TX/SPI1_CS/CPU_CUR_W/RGMII0_TXD1/RMII0_TXD1/PH_EINT4, 37 PH5/UART3_RX/SPI1_CLK/LEDC/RGMII0_TXD0/RMII0_TXD0/PH_EINT5, 38 PH6/UART3_RTS/SPI1_MOSI/SPDIF_IN/RGMII0_TXCK/RMII0_TXCK/PH_EINT6, 39 PH16/I2S3_DOUT0/I2S3_DIN1/RGMII0_RXCK/RMII0_NULL/PH_EINT16, 40 PH14/I2S3_BCLK/RGMII0_RXD3/RMII0_NULL/PH_EINT14, 41 PH15/I2S3_LRCK/RGMII0_RXD2/RMII0_NULL/PH_EINT15, 42 GND, 43 PH1/TWI0_SDA/RGMII0_RXD0/RMII0_RXD0/PH_EINT1, 44 PH0/TWI0_SCK/RGMII0_RXD1/RMII0_RXD1/PH_EINT0, 45 PH2/TWI1_SCK/CPU_CUR_W/RGMII0_RXCTL/RMII0_CRS_DV/PH_EINT2, 46 PH12/DMIC_DATA3/TWI3_SCK/I2S2_DIN0/I2S2_DOUT1/PH_EINT12, 47 PH13/TWI3_SDA/I2S3_MCLK/EPHY0_25/PH_EINT13, 48 PH19/CIR_IN/I2S3_DOUT3/I2S3_DIN3/LEDC/PH, 49 PB0/UART2_TX/SPI2_CS/JTAG_MS/PB_EINT0, 50 PB1/UART2_RX/SPI2_CLK/JTAG_CK/PB_EINT1, 51 PB2/UART2_RTS/SPI2_MOSI/JTAG_DO/PB_EINT2, 52 PB3/UART2_CTS/SPI2_MISO/JTAG_DI/PB_EINT3, 53 PB4/TWI1_SCK/I2S0_MCLK/JTAG_MS_GPU/PB_EI, 54 PB5/TWI1_SDA/I2S0_BCLK/JTAG_CK_GPU/PB_EI, 55 PB6/I2S0_LRCK/JTAG_DO_GPU/PB_EINT6, 56 PB9/UART0_TX/TWI0_SCK/JTAG_DI_GPU/PB_EIN, 57 PB10/UART0_RX/TWI0_SDA/PWM1/PB_EINT10 (power), 58 GND, 59 PG9/UART1_CTS/I2S1_MCLK/PG_EINT9, 60 PG8/UART1_RTS/PG_EINT8, 61 PG7/UART1_RX/PG_EINT7, 62 PG6/UART1_TX/PG_EINT6, 63 GND, 64 PL11/S_CPU_CUR_W/S_CIR_IN/S_PL_EINT11, 65 PL10/S_PWM/S_PL_EINT10, 66 PL9/S_TWI1_SDA/S_PL_EINT9, 67 PL8/S_TWI1_SCK/S_PL_EINT8, 68 PL7/S_JTAG_DI/S_PL_EINT7, 69 PD22/PWM1/TWI0_SCK/PD_EINT22, 70 CHGLED, 71 VCC-3V3, 72 GND, 73 PD0/LCD0_D2/LVDS0_D0P/DSI_DP0/PD_EINT0, 74 PD1/LCD0_D3/LVDS0_D0N/DSI_DM0/PD_EINT1, 75 PD2/LCD0_D4/LVDS0_D1P/DSI_DP1/PD_EINT2, 76 PD3/LCD0_D5/LVDS0_D1N/DSI_DM1/PD_EINT3, 77 PD4/LCD0_D6/LVDS0_D2P/DSI_CKP/PD_EINT4, 78 PD5/LCD0_D7/LVDS0_D2N/DSI_CKM/PD_EINT5, 79 PD6/LCD0_D10/LVDS0_CKP/DSI_DP2/PD_EINT6, 80 PD7/LCD0_D11/LVDS0_CKN/DSI_DM2/PD_EINT7, 81 PD8/LCD0_D12/LVDS0_D3P/DSI_DP3/PD_EINT8, 82 PD9/LCD0_D13/LVDS0_D3N/DSI_DM3/PD_EINT9, 83 PD10/LCD0_D14/LVDS1_D0P/SPI1_CS/PD_EINT1, 84 PD11/LCD0_D15/LVDS1_D0N/SPI1_CLK/PD_EINT, 85 PD12/LCD0_D18/LVDS1_D1P/SPI1_MOSI/PD_EIN, 86 PD13/LCD0_D19/LVDS1_D1N/SPI1_MISO/PD_EIN, 87 PD14/LCD0_D20/LVDS1_D2P/UART3_TX/PD_EINT, 88 PD15/LCD0_D21/LVDS1_D2N/UART3_RX/PD_EINT (power), 89 PD16/LCD0_D22/LVDS1_CKP/PLL_TEST_CKP/UAR, 90 PD17/LCD0_D23/LVDS1_CKN/PLL_TEST_CKN/UAR, 91 PD18/LCD0_CLK/LVDS1_D3P/UART4_TX/PD_EINT, 92 PD19/LCD0_DE/LVDS1_D3N/UART4_RX/PD_EINT1, 93 PD20/LCD0_HSYNC_/PWM2/UART4_RTS/PD_EINT2, 94 PD21/LCD0_VSYNC/PWM3/UART4_CTS/PD_EINT21, 95 PD23/PWM0/TWI0_SDA/PD_EINT23, 96 PC12/NAND_DQS/SPI0_CLK/PC_EINT12 (power), 97 PC7/NAND_RB1/SPI0_CS1/PC_EINT7, 98 PC4/NAND_CE0/SPI0_MISO/PC_EINT4, 99 PC3/NAND_CE1/SPI0_CS0/PC_EINT3, 100 PC2/NAND_CLE/SPI0_MOSI/PC_EINT2, 101 USB1-DP, 102 USB1-DM, 103 PH8/DMIC_CLK/SPI2_CS/I2S2_MCLK/I2S2_DIN2, 104 USB0-DP, 105 USB0-DM, 106 VBAT, 107 VBAT, 108 ST, 109 PWRON, 110 PS, 111 GND, 112 GND, 113 ACIN2, 114 ACIN1, 115 PE9/BIST_RESULT3/I2S2_DIN0/PE_EINT9, 116 PE8/BIST_RESULT2/I2S2_DOUT0/PE_EINT8, 117 PE7/CSI_SM_VS/BIST_RESULT1/I2S2_LRCK/TCO, 118 PE6/BIST_RESULT0/I2S2_BCLK/PE_EINT6, 119 PE4/TWI3_SDA/PE_EINT4, 120 PE3/TWI3_SCK/PE_EINT3, 121 GND, 122 MCSIA_D3N, 123 MCSIA_D3P (power), 124 MCSIA_D2N, 125 MCSIA_D2P, 126 MCSIA_D1N, 127 MCSIA_D1P, 128 MCSIA_D0N (power), 129 MCSIA_D0P (power), 130 MCSIA_CLKN, 131 MCSIA_CLKP, 132 MCSIB_D1N, 133 MCSIB_D1P, 134 MCSIB_D0N, 135 MCSIB_D0P, 136 MCSIB_CLKN, 137 MCSIB_CLKP, 138 PE5/MIPI_MCLK1/PLL_LOCK_DBG/I2S2_MCLK/LE, 139 PE0/MIPI_MCLK0/PE_EINT0, 140 PE1/TWI2_SCK/PE_EINT1, 141 PE2/TWI2_SDA/PE_EINT2, 142 AFVCC-CSI, 143 DVDD-CSI, 144 AVDD-CSI

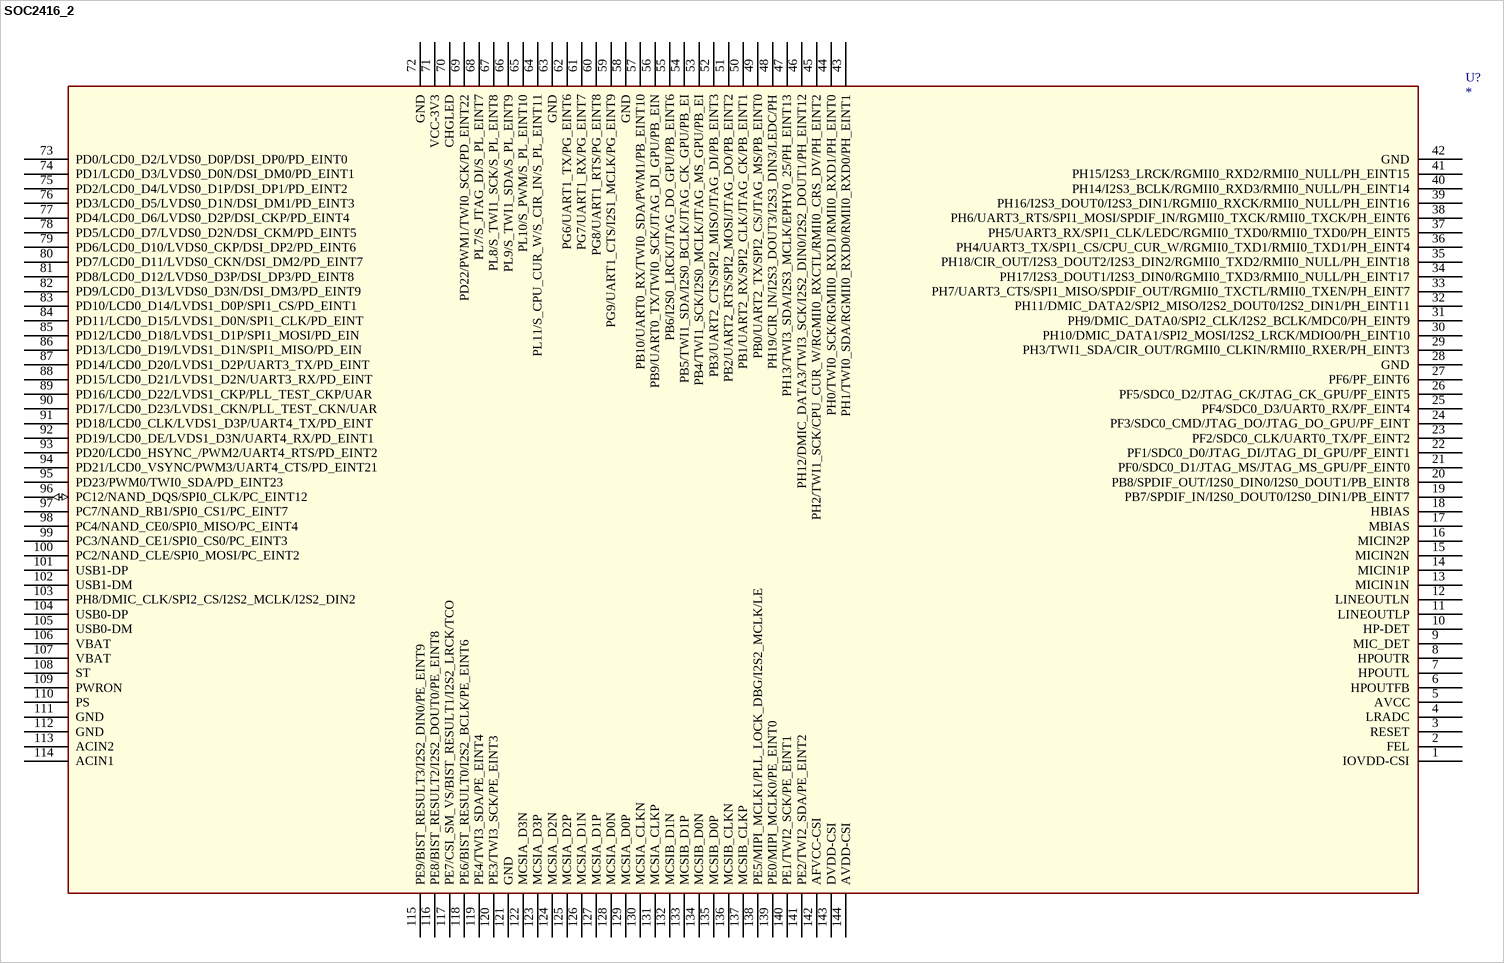
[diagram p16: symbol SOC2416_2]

## SOC2416_2
designator U?
footprint SOC4X4_1MM
pins: 1 IOVDD-CSI, 2 FEL, 3 RESET, 4 LRADC, 5 AVCC, 6 HPOUTFB, 7 HPOUTL, 8 HPOUTR, 9 MIC_DET, 10 HP-DET, 11 LINEOUTLP, 12 LINEOUTLN, 13 MICIN1N, 14 MICIN1P, 15 MICIN2N, 16 MICIN2P, 17 MBIAS, 18 HBIAS, 19 PB7/SPDIF_IN/I2S0_DOUT0/I2S0_DIN1/PB_EINT7, 20 PB8/SPDIF_OUT/I2S0_DIN0/I2S0_DOUT1/PB_EINT8, 21 PF0/SDC0_D1/JTAG_MS/JTAG_MS_GPU/PF_EINT0, 22 PF1/SDC0_D0/JTAG_DI/JTAG_DI_GPU/PF_EINT1, 23 PF2/SDC0_CLK/UART0_TX/PF_EINT2, 24 PF3/SDC0_CMD/JTAG_DO/JTAG_DO_GPU/PF_EINT, 25 PF4/SDC0_D3/UART0_RX/PF_EINT4, 26 PF5/SDC0_D2/JTAG_CK/JTAG_CK_GPU/PF_EINT5, 27 PF6/PF_EINT6, 28 GND, 29 PH3/TWI1_SDA/CIR_OUT/RGMII0_CLKIN/RMII0_RXER/PH_EINT3, 30 PH10/DMIC_DATA1/SPI2_MOSI/I2S2_LRCK/MDIO0/PH_EINT10, 31 PH9/DMIC_DATA0/SPI2_CLK/I2S2_BCLK/MDC0/PH_EINT9, 32 PH11/DMIC_DATA2/SPI2_MISO/I2S2_DOUT0/I2S2_DIN1/PH_EINT11, 33 PH7/UART3_CTS/SPI1_MISO/SPDIF_OUT/RGMII0_TXCTL/RMII0_TXEN/PH_EINT7, 34 PH17/I2S3_DOUT1/I2S3_DIN0/RGMII0_TXD3/RMII0_NULL/PH_EINT17, 35 PH18/CIR_OUT/I2S3_DOUT2/I2S3_DIN2/RGMII0_TXD2/RMII0_NULL/PH_EINT18, 36 PH4/UART3_TX/SPI1_CS/CPU_CUR_W/RGMII0_TXD1/RMII0_TXD1/PH_EINT4, 37 PH5/UART3_RX/SPI1_CLK/LEDC/RGMII0_TXD0/RMII0_TXD0/PH_EINT5, 38 PH6/UART3_RTS/SPI1_MOSI/SPDIF_IN/RGMII0_TXCK/RMII0_TXCK/PH_EINT6, 39 PH16/I2S3_DOUT0/I2S3_DIN1/RGMII0_RXCK/RMII0_NULL/PH_EINT16, 40 PH14/I2S3_BCLK/RGMII0_RXD3/RMII0_NULL/PH_EINT14, 41 PH15/I2S3_LRCK/RGMII0_RXD2/RMII0_NULL/PH_EINT15, 42 GND, 43 PH1/TWI0_SDA/RGMII0_RXD0/RMII0_RXD0/PH_EINT1, 44 PH0/TWI0_SCK/RGMII0_RXD1/RMII0_RXD1/PH_EINT0, 45 PH2/TWI1_SCK/CPU_CUR_W/RGMII0_RXCTL/RMII0_CRS_DV/PH_EINT2, 46 PH12/DMIC_DATA3/TWI3_SCK/I2S2_DIN0/I2S2_DOUT1/PH_EINT12, 47 PH13/TWI3_SDA/I2S3_MCLK/EPHY0_25/PH_EINT13, 48 PH19/CIR_IN/I2S3_DOUT3/I2S3_DIN3/LEDC/PH, 49 PB0/UART2_TX/SPI2_CS/JTAG_MS/PB_EINT0, 50 PB1/UART2_RX/SPI2_CLK/JTAG_CK/PB_EINT1, 51 PB2/UART2_RTS/SPI2_MOSI/JTAG_DO/PB_EINT2, 52 PB3/UART2_CTS/SPI2_MISO/JTAG_DI/PB_EINT3, 53 PB4/TWI1_SCK/I2S0_MCLK/JTAG_MS_GPU/PB_EI, 54 PB5/TWI1_SDA/I2S0_BCLK/JTAG_CK_GPU/PB_EI, 55 PB6/I2S0_LRCK/JTAG_DO_GPU/PB_EINT6, 56 PB9/UART0_TX/TWI0_SCK/JTAG_DI_GPU/PB_EIN, 57 PB10/UART0_RX/TWI0_SDA/PWM1/PB_EINT10 (power), 58 GND, 59 PG9/UART1_CTS/I2S1_MCLK/PG_EINT9, 60 PG8/UART1_RTS/PG_EINT8, 61 PG7/UART1_RX/PG_EINT7, 62 PG6/UART1_TX/PG_EINT6, 63 GND, 64 PL11/S_CPU_CUR_W/S_CIR_IN/S_PL_EINT11, 65 PL10/S_PWM/S_PL_EINT10, 66 PL9/S_TWI1_SDA/S_PL_EINT9, 67 PL8/S_TWI1_SCK/S_PL_EINT8, 68 PL7/S_JTAG_DI/S_PL_EINT7, 69 PD22/PWM1/TWI0_SCK/PD_EINT22, 70 CHGLED, 71 VCC-3V3, 72 GND, 73 PD0/LCD0_D2/LVDS0_D0P/DSI_DP0/PD_EINT0, 74 PD1/LCD0_D3/LVDS0_D0N/DSI_DM0/PD_EINT1, 75 PD2/LCD0_D4/LVDS0_D1P/DSI_DP1/PD_EINT2, 76 PD3/LCD0_D5/LVDS0_D1N/DSI_DM1/PD_EINT3, 77 PD4/LCD0_D6/LVDS0_D2P/DSI_CKP/PD_EINT4, 78 PD5/LCD0_D7/LVDS0_D2N/DSI_CKM/PD_EINT5, 79 PD6/LCD0_D10/LVDS0_CKP/DSI_DP2/PD_EINT6, 80 PD7/LCD0_D11/LVDS0_CKN/DSI_DM2/PD_EINT7, 81 PD8/LCD0_D12/LVDS0_D3P/DSI_DP3/PD_EINT8, 82 PD9/LCD0_D13/LVDS0_D3N/DSI_DM3/PD_EINT9, 83 PD10/LCD0_D14/LVDS1_D0P/SPI1_CS/PD_EINT1, 84 PD11/LCD0_D15/LVDS1_D0N/SPI1_CLK/PD_EINT, 85 PD12/LCD0_D18/LVDS1_D1P/SPI1_MOSI/PD_EIN, 86 PD13/LCD0_D19/LVDS1_D1N/SPI1_MISO/PD_EIN, 87 PD14/LCD0_D20/LVDS1_D2P/UART3_TX/PD_EINT, 88 PD15/LCD0_D21/LVDS1_D2N/UART3_RX/PD_EINT (power), 89 PD16/LCD0_D22/LVDS1_CKP/PLL_TEST_CKP/UAR, 90 PD17/LCD0_D23/LVDS1_CKN/PLL_TEST_CKN/UAR, 91 PD18/LCD0_CLK/LVDS1_D3P/UART4_TX/PD_EINT, 92 PD19/LCD0_DE/LVDS1_D3N/UART4_RX/PD_EINT1, 93 PD20/LCD0_HSYNC_/PWM2/UART4_RTS/PD_EINT2, 94 PD21/LCD0_VSYNC/PWM3/UART4_CTS/PD_EINT21, 95 PD23/PWM0/TWI0_SDA/PD_EINT23, 96 PC12/NAND_DQS/SPI0_CLK/PC_EINT12 (io), 97 PC7/NAND_RB1/SPI0_CS1/PC_EINT7, 98 PC4/NAND_CE0/SPI0_MISO/PC_EINT4, 99 PC3/NAND_CE1/SPI0_CS0/PC_EINT3, 100 PC2/NAND_CLE/SPI0_MOSI/PC_EINT2, 101 USB1-DP, 102 USB1-DM, 103 PH8/DMIC_CLK/SPI2_CS/I2S2_MCLK/I2S2_DIN2, 104 USB0-DP, 105 USB0-DM, 106 VBAT, 107 VBAT, 108 ST, 109 PWRON, 110 PS, 111 GND, 112 GND, 113 ACIN2, 114 ACIN1, 115 PE9/BIST_RESULT3/I2S2_DIN0/PE_EINT9, 116 PE8/BIST_RESULT2/I2S2_DOUT0/PE_EINT8, 117 PE7/CSI_SM_VS/BIST_RESULT1/I2S2_LRCK/TCO, 118 PE6/BIST_RESULT0/I2S2_BCLK/PE_EINT6, 119 PE4/TWI3_SDA/PE_EINT4, 120 PE3/TWI3_SCK/PE_EINT3, 121 GND, 122 MCSIA_D3N, 123 MCSIA_D3P (power), 124 MCSIA_D2N, 125 MCSIA_D2P, 126 MCSIA_D1N, 127 MCSIA_D1P, 128 MCSIA_D0N (power), 129 MCSIA_D0P (power), 130 MCSIA_CLKN, 131 MCSIA_CLKP, 132 MCSIB_D1N, 133 MCSIB_D1P, 134 MCSIB_D0N, 135 MCSIB_D0P, 136 MCSIB_CLKN, 137 MCSIB_CLKP, 138 PE5/MIPI_MCLK1/PLL_LOCK_DBG/I2S2_MCLK/LE, 139 PE0/MIPI_MCLK0/PE_EINT0, 140 PE1/TWI2_SCK/PE_EINT1, 141 PE2/TWI2_SDA/PE_EINT2, 142 AFVCC-CSI, 143 DVDD-CSI, 144 AVDD-CSI

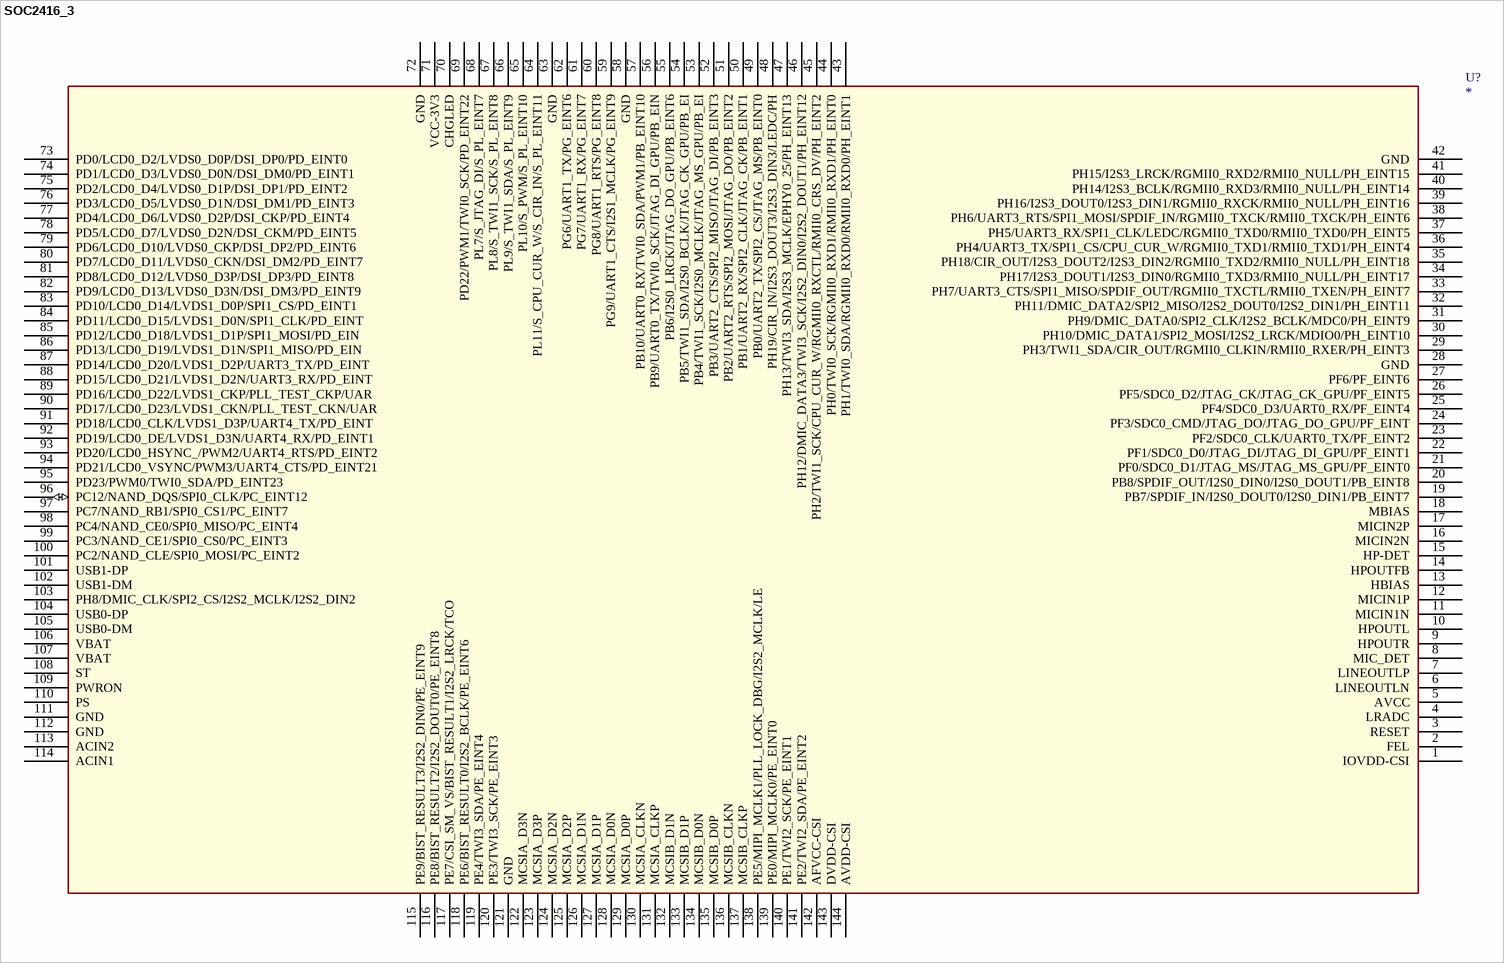
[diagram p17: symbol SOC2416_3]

## SOC2416_3
designator U?
footprint SOC4X4_1MM
pins: 1 IOVDD-CSI, 2 FEL, 3 RESET, 4 LRADC, 5 AVCC, 6 LINEOUTLN, 7 LINEOUTLP, 8 MIC_DET, 9 HPOUTR, 10 HPOUTL, 11 MICIN1N, 12 MICIN1P, 13 HBIAS, 14 HPOUTFB, 15 HP-DET, 16 MICIN2N, 17 MICIN2P, 18 MBIAS, 19 PB7/SPDIF_IN/I2S0_DOUT0/I2S0_DIN1/PB_EINT7, 20 PB8/SPDIF_OUT/I2S0_DIN0/I2S0_DOUT1/PB_EINT8, 21 PF0/SDC0_D1/JTAG_MS/JTAG_MS_GPU/PF_EINT0, 22 PF1/SDC0_D0/JTAG_DI/JTAG_DI_GPU/PF_EINT1, 23 PF2/SDC0_CLK/UART0_TX/PF_EINT2, 24 PF3/SDC0_CMD/JTAG_DO/JTAG_DO_GPU/PF_EINT, 25 PF4/SDC0_D3/UART0_RX/PF_EINT4, 26 PF5/SDC0_D2/JTAG_CK/JTAG_CK_GPU/PF_EINT5, 27 PF6/PF_EINT6, 28 GND, 29 PH3/TWI1_SDA/CIR_OUT/RGMII0_CLKIN/RMII0_RXER/PH_EINT3, 30 PH10/DMIC_DATA1/SPI2_MOSI/I2S2_LRCK/MDIO0/PH_EINT10, 31 PH9/DMIC_DATA0/SPI2_CLK/I2S2_BCLK/MDC0/PH_EINT9, 32 PH11/DMIC_DATA2/SPI2_MISO/I2S2_DOUT0/I2S2_DIN1/PH_EINT11, 33 PH7/UART3_CTS/SPI1_MISO/SPDIF_OUT/RGMII0_TXCTL/RMII0_TXEN/PH_EINT7, 34 PH17/I2S3_DOUT1/I2S3_DIN0/RGMII0_TXD3/RMII0_NULL/PH_EINT17, 35 PH18/CIR_OUT/I2S3_DOUT2/I2S3_DIN2/RGMII0_TXD2/RMII0_NULL/PH_EINT18, 36 PH4/UART3_TX/SPI1_CS/CPU_CUR_W/RGMII0_TXD1/RMII0_TXD1/PH_EINT4, 37 PH5/UART3_RX/SPI1_CLK/LEDC/RGMII0_TXD0/RMII0_TXD0/PH_EINT5, 38 PH6/UART3_RTS/SPI1_MOSI/SPDIF_IN/RGMII0_TXCK/RMII0_TXCK/PH_EINT6, 39 PH16/I2S3_DOUT0/I2S3_DIN1/RGMII0_RXCK/RMII0_NULL/PH_EINT16, 40 PH14/I2S3_BCLK/RGMII0_RXD3/RMII0_NULL/PH_EINT14, 41 PH15/I2S3_LRCK/RGMII0_RXD2/RMII0_NULL/PH_EINT15, 42 GND, 43 PH1/TWI0_SDA/RGMII0_RXD0/RMII0_RXD0/PH_EINT1, 44 PH0/TWI0_SCK/RGMII0_RXD1/RMII0_RXD1/PH_EINT0, 45 PH2/TWI1_SCK/CPU_CUR_W/RGMII0_RXCTL/RMII0_CRS_DV/PH_EINT2, 46 PH12/DMIC_DATA3/TWI3_SCK/I2S2_DIN0/I2S2_DOUT1/PH_EINT12, 47 PH13/TWI3_SDA/I2S3_MCLK/EPHY0_25/PH_EINT13, 48 PH19/CIR_IN/I2S3_DOUT3/I2S3_DIN3/LEDC/PH, 49 PB0/UART2_TX/SPI2_CS/JTAG_MS/PB_EINT0, 50 PB1/UART2_RX/SPI2_CLK/JTAG_CK/PB_EINT1, 51 PB2/UART2_RTS/SPI2_MOSI/JTAG_DO/PB_EINT2, 52 PB3/UART2_CTS/SPI2_MISO/JTAG_DI/PB_EINT3, 53 PB4/TWI1_SCK/I2S0_MCLK/JTAG_MS_GPU/PB_EI, 54 PB5/TWI1_SDA/I2S0_BCLK/JTAG_CK_GPU/PB_EI, 55 PB6/I2S0_LRCK/JTAG_DO_GPU/PB_EINT6, 56 PB9/UART0_TX/TWI0_SCK/JTAG_DI_GPU/PB_EIN, 57 PB10/UART0_RX/TWI0_SDA/PWM1/PB_EINT10 (power), 58 GND, 59 PG9/UART1_CTS/I2S1_MCLK/PG_EINT9, 60 PG8/UART1_RTS/PG_EINT8, 61 PG7/UART1_RX/PG_EINT7, 62 PG6/UART1_TX/PG_EINT6, 63 GND, 64 PL11/S_CPU_CUR_W/S_CIR_IN/S_PL_EINT11, 65 PL10/S_PWM/S_PL_EINT10, 66 PL9/S_TWI1_SDA/S_PL_EINT9, 67 PL8/S_TWI1_SCK/S_PL_EINT8, 68 PL7/S_JTAG_DI/S_PL_EINT7, 69 PD22/PWM1/TWI0_SCK/PD_EINT22, 70 CHGLED, 71 VCC-3V3, 72 GND, 73 PD0/LCD0_D2/LVDS0_D0P/DSI_DP0/PD_EINT0, 74 PD1/LCD0_D3/LVDS0_D0N/DSI_DM0/PD_EINT1, 75 PD2/LCD0_D4/LVDS0_D1P/DSI_DP1/PD_EINT2, 76 PD3/LCD0_D5/LVDS0_D1N/DSI_DM1/PD_EINT3, 77 PD4/LCD0_D6/LVDS0_D2P/DSI_CKP/PD_EINT4, 78 PD5/LCD0_D7/LVDS0_D2N/DSI_CKM/PD_EINT5, 79 PD6/LCD0_D10/LVDS0_CKP/DSI_DP2/PD_EINT6, 80 PD7/LCD0_D11/LVDS0_CKN/DSI_DM2/PD_EINT7, 81 PD8/LCD0_D12/LVDS0_D3P/DSI_DP3/PD_EINT8, 82 PD9/LCD0_D13/LVDS0_D3N/DSI_DM3/PD_EINT9, 83 PD10/LCD0_D14/LVDS1_D0P/SPI1_CS/PD_EINT1, 84 PD11/LCD0_D15/LVDS1_D0N/SPI1_CLK/PD_EINT, 85 PD12/LCD0_D18/LVDS1_D1P/SPI1_MOSI/PD_EIN, 86 PD13/LCD0_D19/LVDS1_D1N/SPI1_MISO/PD_EIN, 87 PD14/LCD0_D20/LVDS1_D2P/UART3_TX/PD_EINT, 88 PD15/LCD0_D21/LVDS1_D2N/UART3_RX/PD_EINT (power), 89 PD16/LCD0_D22/LVDS1_CKP/PLL_TEST_CKP/UAR, 90 PD17/LCD0_D23/LVDS1_CKN/PLL_TEST_CKN/UAR, 91 PD18/LCD0_CLK/LVDS1_D3P/UART4_TX/PD_EINT, 92 PD19/LCD0_DE/LVDS1_D3N/UART4_RX/PD_EINT1, 93 PD20/LCD0_HSYNC_/PWM2/UART4_RTS/PD_EINT2, 94 PD21/LCD0_VSYNC/PWM3/UART4_CTS/PD_EINT21, 95 PD23/PWM0/TWI0_SDA/PD_EINT23, 96 PC12/NAND_DQS/SPI0_CLK/PC_EINT12 (io), 97 PC7/NAND_RB1/SPI0_CS1/PC_EINT7, 98 PC4/NAND_CE0/SPI0_MISO/PC_EINT4, 99 PC3/NAND_CE1/SPI0_CS0/PC_EINT3, 100 PC2/NAND_CLE/SPI0_MOSI/PC_EINT2, 101 USB1-DP, 102 USB1-DM, 103 PH8/DMIC_CLK/SPI2_CS/I2S2_MCLK/I2S2_DIN2, 104 USB0-DP, 105 USB0-DM, 106 VBAT, 107 VBAT, 108 ST, 109 PWRON, 110 PS, 111 GND, 112 GND, 113 ACIN2, 114 ACIN1, 115 PE9/BIST_RESULT3/I2S2_DIN0/PE_EINT9, 116 PE8/BIST_RESULT2/I2S2_DOUT0/PE_EINT8, 117 PE7/CSI_SM_VS/BIST_RESULT1/I2S2_LRCK/TCO, 118 PE6/BIST_RESULT0/I2S2_BCLK/PE_EINT6, 119 PE4/TWI3_SDA/PE_EINT4, 120 PE3/TWI3_SCK/PE_EINT3, 121 GND, 122 MCSIA_D3N, 123 MCSIA_D3P (power), 124 MCSIA_D2N, 125 MCSIA_D2P, 126 MCSIA_D1N, 127 MCSIA_D1P, 128 MCSIA_D0N (power), 129 MCSIA_D0P (power), 130 MCSIA_CLKN, 131 MCSIA_CLKP, 132 MCSIB_D1N, 133 MCSIB_D1P, 134 MCSIB_D0N, 135 MCSIB_D0P, 136 MCSIB_CLKN, 137 MCSIB_CLKP, 138 PE5/MIPI_MCLK1/PLL_LOCK_DBG/I2S2_MCLK/LE, 139 PE0/MIPI_MCLK0/PE_EINT0, 140 PE1/TWI2_SCK/PE_EINT1, 141 PE2/TWI2_SDA/PE_EINT2, 142 AFVCC-CSI, 143 DVDD-CSI, 144 AVDD-CSI

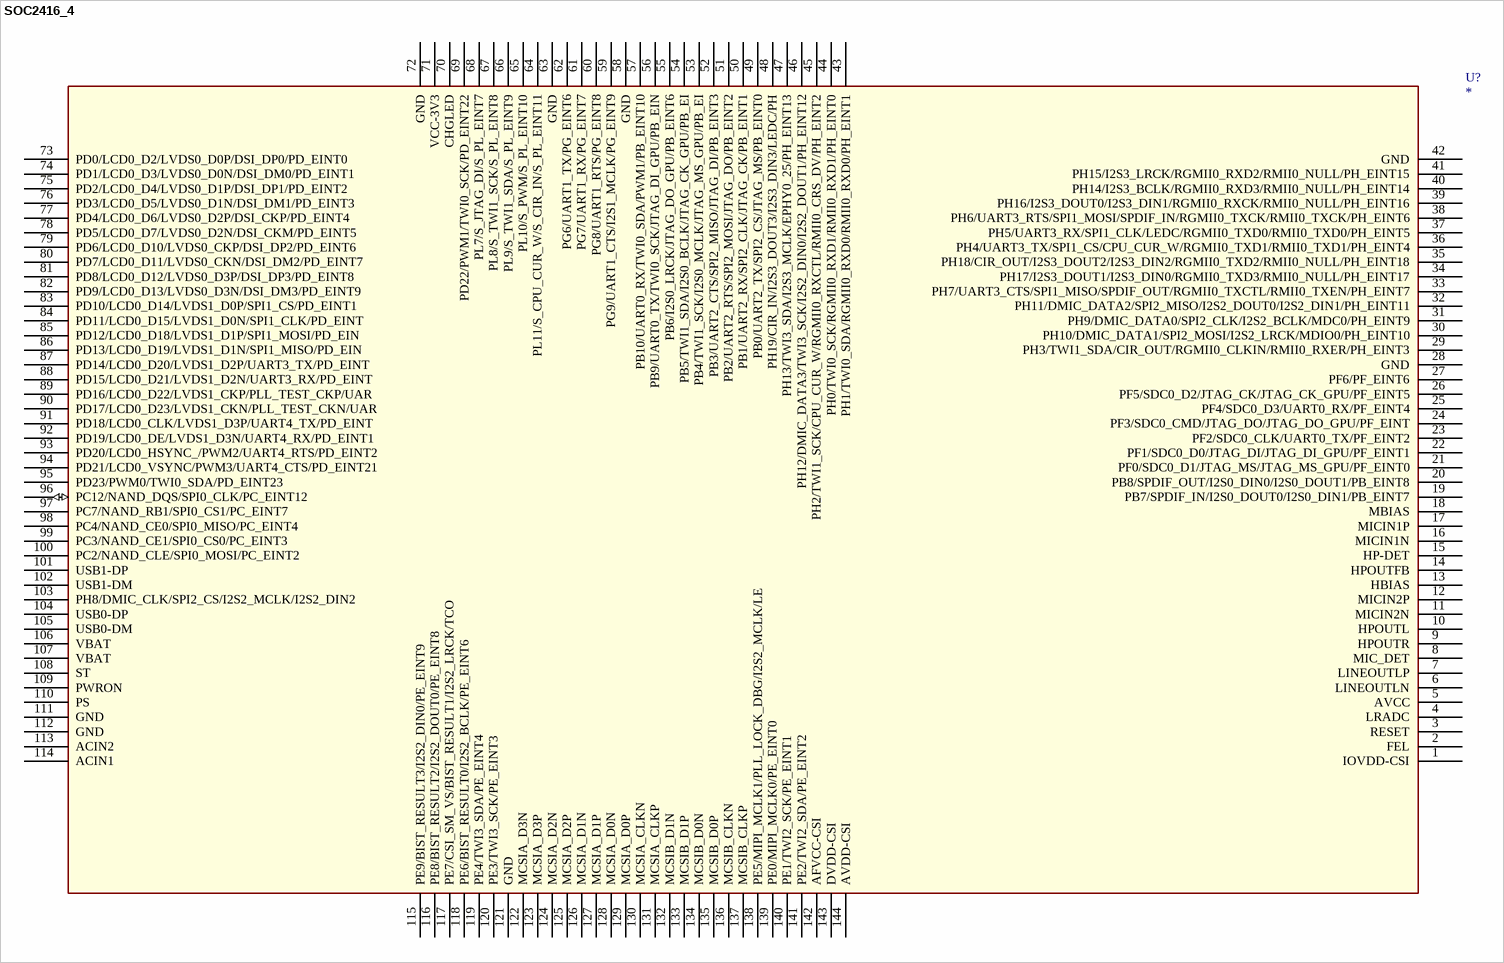
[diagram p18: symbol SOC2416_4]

## SOC2416_4
designator U?
footprint SOC4X4_1MM
pins: 1 IOVDD-CSI, 2 FEL, 3 RESET, 4 LRADC, 5 AVCC, 6 LINEOUTLN, 7 LINEOUTLP, 8 MIC_DET, 9 HPOUTR, 10 HPOUTL, 11 MICIN2N, 12 MICIN2P, 13 HBIAS, 14 HPOUTFB, 15 HP-DET, 16 MICIN1N, 17 MICIN1P, 18 MBIAS, 19 PB7/SPDIF_IN/I2S0_DOUT0/I2S0_DIN1/PB_EINT7, 20 PB8/SPDIF_OUT/I2S0_DIN0/I2S0_DOUT1/PB_EINT8, 21 PF0/SDC0_D1/JTAG_MS/JTAG_MS_GPU/PF_EINT0, 22 PF1/SDC0_D0/JTAG_DI/JTAG_DI_GPU/PF_EINT1, 23 PF2/SDC0_CLK/UART0_TX/PF_EINT2, 24 PF3/SDC0_CMD/JTAG_DO/JTAG_DO_GPU/PF_EINT, 25 PF4/SDC0_D3/UART0_RX/PF_EINT4, 26 PF5/SDC0_D2/JTAG_CK/JTAG_CK_GPU/PF_EINT5, 27 PF6/PF_EINT6, 28 GND, 29 PH3/TWI1_SDA/CIR_OUT/RGMII0_CLKIN/RMII0_RXER/PH_EINT3, 30 PH10/DMIC_DATA1/SPI2_MOSI/I2S2_LRCK/MDIO0/PH_EINT10, 31 PH9/DMIC_DATA0/SPI2_CLK/I2S2_BCLK/MDC0/PH_EINT9, 32 PH11/DMIC_DATA2/SPI2_MISO/I2S2_DOUT0/I2S2_DIN1/PH_EINT11, 33 PH7/UART3_CTS/SPI1_MISO/SPDIF_OUT/RGMII0_TXCTL/RMII0_TXEN/PH_EINT7, 34 PH17/I2S3_DOUT1/I2S3_DIN0/RGMII0_TXD3/RMII0_NULL/PH_EINT17, 35 PH18/CIR_OUT/I2S3_DOUT2/I2S3_DIN2/RGMII0_TXD2/RMII0_NULL/PH_EINT18, 36 PH4/UART3_TX/SPI1_CS/CPU_CUR_W/RGMII0_TXD1/RMII0_TXD1/PH_EINT4, 37 PH5/UART3_RX/SPI1_CLK/LEDC/RGMII0_TXD0/RMII0_TXD0/PH_EINT5, 38 PH6/UART3_RTS/SPI1_MOSI/SPDIF_IN/RGMII0_TXCK/RMII0_TXCK/PH_EINT6, 39 PH16/I2S3_DOUT0/I2S3_DIN1/RGMII0_RXCK/RMII0_NULL/PH_EINT16, 40 PH14/I2S3_BCLK/RGMII0_RXD3/RMII0_NULL/PH_EINT14, 41 PH15/I2S3_LRCK/RGMII0_RXD2/RMII0_NULL/PH_EINT15, 42 GND, 43 PH1/TWI0_SDA/RGMII0_RXD0/RMII0_RXD0/PH_EINT1, 44 PH0/TWI0_SCK/RGMII0_RXD1/RMII0_RXD1/PH_EINT0, 45 PH2/TWI1_SCK/CPU_CUR_W/RGMII0_RXCTL/RMII0_CRS_DV/PH_EINT2, 46 PH12/DMIC_DATA3/TWI3_SCK/I2S2_DIN0/I2S2_DOUT1/PH_EINT12, 47 PH13/TWI3_SDA/I2S3_MCLK/EPHY0_25/PH_EINT13, 48 PH19/CIR_IN/I2S3_DOUT3/I2S3_DIN3/LEDC/PH, 49 PB0/UART2_TX/SPI2_CS/JTAG_MS/PB_EINT0, 50 PB1/UART2_RX/SPI2_CLK/JTAG_CK/PB_EINT1, 51 PB2/UART2_RTS/SPI2_MOSI/JTAG_DO/PB_EINT2, 52 PB3/UART2_CTS/SPI2_MISO/JTAG_DI/PB_EINT3, 53 PB4/TWI1_SCK/I2S0_MCLK/JTAG_MS_GPU/PB_EI, 54 PB5/TWI1_SDA/I2S0_BCLK/JTAG_CK_GPU/PB_EI, 55 PB6/I2S0_LRCK/JTAG_DO_GPU/PB_EINT6, 56 PB9/UART0_TX/TWI0_SCK/JTAG_DI_GPU/PB_EIN, 57 PB10/UART0_RX/TWI0_SDA/PWM1/PB_EINT10 (power), 58 GND, 59 PG9/UART1_CTS/I2S1_MCLK/PG_EINT9, 60 PG8/UART1_RTS/PG_EINT8, 61 PG7/UART1_RX/PG_EINT7, 62 PG6/UART1_TX/PG_EINT6, 63 GND, 64 PL11/S_CPU_CUR_W/S_CIR_IN/S_PL_EINT11, 65 PL10/S_PWM/S_PL_EINT10, 66 PL9/S_TWI1_SDA/S_PL_EINT9, 67 PL8/S_TWI1_SCK/S_PL_EINT8, 68 PL7/S_JTAG_DI/S_PL_EINT7, 69 PD22/PWM1/TWI0_SCK/PD_EINT22, 70 CHGLED, 71 VCC-3V3, 72 GND, 73 PD0/LCD0_D2/LVDS0_D0P/DSI_DP0/PD_EINT0, 74 PD1/LCD0_D3/LVDS0_D0N/DSI_DM0/PD_EINT1, 75 PD2/LCD0_D4/LVDS0_D1P/DSI_DP1/PD_EINT2, 76 PD3/LCD0_D5/LVDS0_D1N/DSI_DM1/PD_EINT3, 77 PD4/LCD0_D6/LVDS0_D2P/DSI_CKP/PD_EINT4, 78 PD5/LCD0_D7/LVDS0_D2N/DSI_CKM/PD_EINT5, 79 PD6/LCD0_D10/LVDS0_CKP/DSI_DP2/PD_EINT6, 80 PD7/LCD0_D11/LVDS0_CKN/DSI_DM2/PD_EINT7, 81 PD8/LCD0_D12/LVDS0_D3P/DSI_DP3/PD_EINT8, 82 PD9/LCD0_D13/LVDS0_D3N/DSI_DM3/PD_EINT9, 83 PD10/LCD0_D14/LVDS1_D0P/SPI1_CS/PD_EINT1, 84 PD11/LCD0_D15/LVDS1_D0N/SPI1_CLK/PD_EINT, 85 PD12/LCD0_D18/LVDS1_D1P/SPI1_MOSI/PD_EIN, 86 PD13/LCD0_D19/LVDS1_D1N/SPI1_MISO/PD_EIN, 87 PD14/LCD0_D20/LVDS1_D2P/UART3_TX/PD_EINT, 88 PD15/LCD0_D21/LVDS1_D2N/UART3_RX/PD_EINT (power), 89 PD16/LCD0_D22/LVDS1_CKP/PLL_TEST_CKP/UAR, 90 PD17/LCD0_D23/LVDS1_CKN/PLL_TEST_CKN/UAR, 91 PD18/LCD0_CLK/LVDS1_D3P/UART4_TX/PD_EINT, 92 PD19/LCD0_DE/LVDS1_D3N/UART4_RX/PD_EINT1, 93 PD20/LCD0_HSYNC_/PWM2/UART4_RTS/PD_EINT2, 94 PD21/LCD0_VSYNC/PWM3/UART4_CTS/PD_EINT21, 95 PD23/PWM0/TWI0_SDA/PD_EINT23, 96 PC12/NAND_DQS/SPI0_CLK/PC_EINT12 (io), 97 PC7/NAND_RB1/SPI0_CS1/PC_EINT7, 98 PC4/NAND_CE0/SPI0_MISO/PC_EINT4, 99 PC3/NAND_CE1/SPI0_CS0/PC_EINT3, 100 PC2/NAND_CLE/SPI0_MOSI/PC_EINT2, 101 USB1-DP, 102 USB1-DM, 103 PH8/DMIC_CLK/SPI2_CS/I2S2_MCLK/I2S2_DIN2, 104 USB0-DP, 105 USB0-DM, 106 VBAT, 107 VBAT, 108 ST, 109 PWRON, 110 PS, 111 GND, 112 GND, 113 ACIN2, 114 ACIN1, 115 PE9/BIST_RESULT3/I2S2_DIN0/PE_EINT9, 116 PE8/BIST_RESULT2/I2S2_DOUT0/PE_EINT8, 117 PE7/CSI_SM_VS/BIST_RESULT1/I2S2_LRCK/TCO, 118 PE6/BIST_RESULT0/I2S2_BCLK/PE_EINT6, 119 PE4/TWI3_SDA/PE_EINT4, 120 PE3/TWI3_SCK/PE_EINT3, 121 GND, 122 MCSIA_D3N, 123 MCSIA_D3P (power), 124 MCSIA_D2N, 125 MCSIA_D2P, 126 MCSIA_D1N, 127 MCSIA_D1P, 128 MCSIA_D0N (power), 129 MCSIA_D0P (power), 130 MCSIA_CLKN, 131 MCSIA_CLKP, 132 MCSIB_D1N, 133 MCSIB_D1P, 134 MCSIB_D0N, 135 MCSIB_D0P, 136 MCSIB_CLKN, 137 MCSIB_CLKP, 138 PE5/MIPI_MCLK1/PLL_LOCK_DBG/I2S2_MCLK/LE, 139 PE0/MIPI_MCLK0/PE_EINT0, 140 PE1/TWI2_SCK/PE_EINT1, 141 PE2/TWI2_SDA/PE_EINT2, 142 AFVCC-CSI, 143 DVDD-CSI, 144 AVDD-CSI

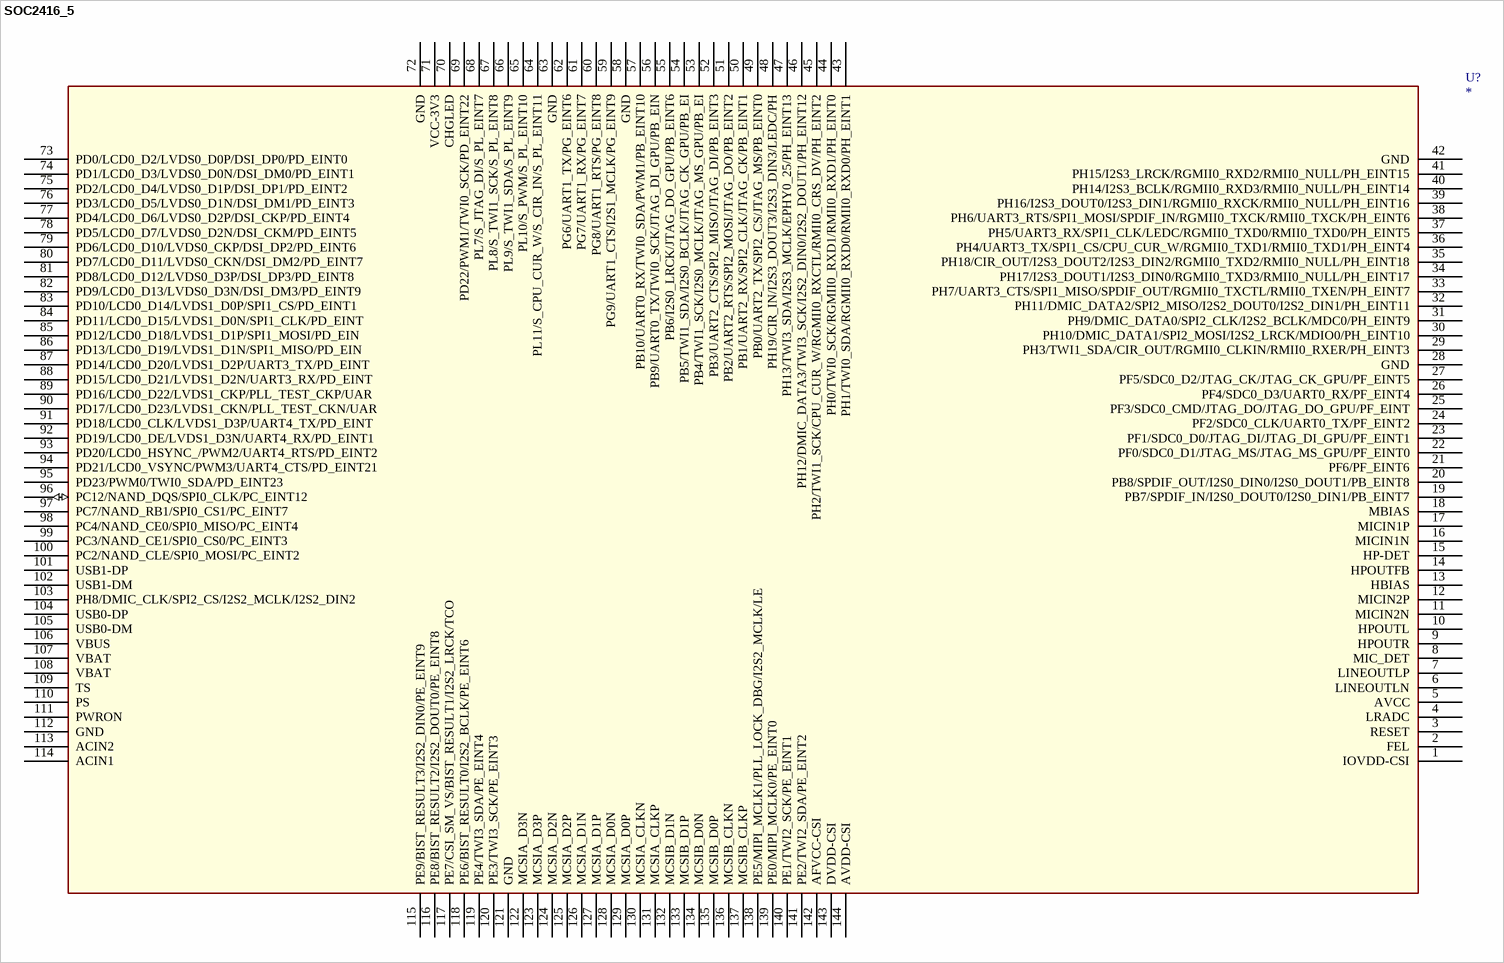
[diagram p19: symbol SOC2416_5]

## SOC2416_5
designator U?
footprint SOC4X4_1MM
pins: 1 IOVDD-CSI, 2 FEL, 3 RESET, 4 LRADC, 5 AVCC, 6 LINEOUTLN, 7 LINEOUTLP, 8 MIC_DET, 9 HPOUTR, 10 HPOUTL, 11 MICIN2N, 12 MICIN2P, 13 HBIAS, 14 HPOUTFB, 15 HP-DET, 16 MICIN1N, 17 MICIN1P, 18 MBIAS, 19 PB7/SPDIF_IN/I2S0_DOUT0/I2S0_DIN1/PB_EINT7, 20 PB8/SPDIF_OUT/I2S0_DIN0/I2S0_DOUT1/PB_EINT8, 21 PF6/PF_EINT6, 22 PF0/SDC0_D1/JTAG_MS/JTAG_MS_GPU/PF_EINT0, 23 PF1/SDC0_D0/JTAG_DI/JTAG_DI_GPU/PF_EINT1, 24 PF2/SDC0_CLK/UART0_TX/PF_EINT2, 25 PF3/SDC0_CMD/JTAG_DO/JTAG_DO_GPU/PF_EINT, 26 PF4/SDC0_D3/UART0_RX/PF_EINT4, 27 PF5/SDC0_D2/JTAG_CK/JTAG_CK_GPU/PF_EINT5, 28 GND, 29 PH3/TWI1_SDA/CIR_OUT/RGMII0_CLKIN/RMII0_RXER/PH_EINT3, 30 PH10/DMIC_DATA1/SPI2_MOSI/I2S2_LRCK/MDIO0/PH_EINT10, 31 PH9/DMIC_DATA0/SPI2_CLK/I2S2_BCLK/MDC0/PH_EINT9, 32 PH11/DMIC_DATA2/SPI2_MISO/I2S2_DOUT0/I2S2_DIN1/PH_EINT11, 33 PH7/UART3_CTS/SPI1_MISO/SPDIF_OUT/RGMII0_TXCTL/RMII0_TXEN/PH_EINT7, 34 PH17/I2S3_DOUT1/I2S3_DIN0/RGMII0_TXD3/RMII0_NULL/PH_EINT17, 35 PH18/CIR_OUT/I2S3_DOUT2/I2S3_DIN2/RGMII0_TXD2/RMII0_NULL/PH_EINT18, 36 PH4/UART3_TX/SPI1_CS/CPU_CUR_W/RGMII0_TXD1/RMII0_TXD1/PH_EINT4, 37 PH5/UART3_RX/SPI1_CLK/LEDC/RGMII0_TXD0/RMII0_TXD0/PH_EINT5, 38 PH6/UART3_RTS/SPI1_MOSI/SPDIF_IN/RGMII0_TXCK/RMII0_TXCK/PH_EINT6, 39 PH16/I2S3_DOUT0/I2S3_DIN1/RGMII0_RXCK/RMII0_NULL/PH_EINT16, 40 PH14/I2S3_BCLK/RGMII0_RXD3/RMII0_NULL/PH_EINT14, 41 PH15/I2S3_LRCK/RGMII0_RXD2/RMII0_NULL/PH_EINT15, 42 GND, 43 PH1/TWI0_SDA/RGMII0_RXD0/RMII0_RXD0/PH_EINT1, 44 PH0/TWI0_SCK/RGMII0_RXD1/RMII0_RXD1/PH_EINT0, 45 PH2/TWI1_SCK/CPU_CUR_W/RGMII0_RXCTL/RMII0_CRS_DV/PH_EINT2, 46 PH12/DMIC_DATA3/TWI3_SCK/I2S2_DIN0/I2S2_DOUT1/PH_EINT12, 47 PH13/TWI3_SDA/I2S3_MCLK/EPHY0_25/PH_EINT13, 48 PH19/CIR_IN/I2S3_DOUT3/I2S3_DIN3/LEDC/PH, 49 PB0/UART2_TX/SPI2_CS/JTAG_MS/PB_EINT0, 50 PB1/UART2_RX/SPI2_CLK/JTAG_CK/PB_EINT1, 51 PB2/UART2_RTS/SPI2_MOSI/JTAG_DO/PB_EINT2, 52 PB3/UART2_CTS/SPI2_MISO/JTAG_DI/PB_EINT3, 53 PB4/TWI1_SCK/I2S0_MCLK/JTAG_MS_GPU/PB_EI, 54 PB5/TWI1_SDA/I2S0_BCLK/JTAG_CK_GPU/PB_EI, 55 PB6/I2S0_LRCK/JTAG_DO_GPU/PB_EINT6, 56 PB9/UART0_TX/TWI0_SCK/JTAG_DI_GPU/PB_EIN, 57 PB10/UART0_RX/TWI0_SDA/PWM1/PB_EINT10 (power), 58 GND, 59 PG9/UART1_CTS/I2S1_MCLK/PG_EINT9, 60 PG8/UART1_RTS/PG_EINT8, 61 PG7/UART1_RX/PG_EINT7, 62 PG6/UART1_TX/PG_EINT6, 63 GND, 64 PL11/S_CPU_CUR_W/S_CIR_IN/S_PL_EINT11, 65 PL10/S_PWM/S_PL_EINT10, 66 PL9/S_TWI1_SDA/S_PL_EINT9, 67 PL8/S_TWI1_SCK/S_PL_EINT8, 68 PL7/S_JTAG_DI/S_PL_EINT7, 69 PD22/PWM1/TWI0_SCK/PD_EINT22, 70 CHGLED, 71 VCC-3V3, 72 GND, 73 PD0/LCD0_D2/LVDS0_D0P/DSI_DP0/PD_EINT0, 74 PD1/LCD0_D3/LVDS0_D0N/DSI_DM0/PD_EINT1, 75 PD2/LCD0_D4/LVDS0_D1P/DSI_DP1/PD_EINT2, 76 PD3/LCD0_D5/LVDS0_D1N/DSI_DM1/PD_EINT3, 77 PD4/LCD0_D6/LVDS0_D2P/DSI_CKP/PD_EINT4, 78 PD5/LCD0_D7/LVDS0_D2N/DSI_CKM/PD_EINT5, 79 PD6/LCD0_D10/LVDS0_CKP/DSI_DP2/PD_EINT6, 80 PD7/LCD0_D11/LVDS0_CKN/DSI_DM2/PD_EINT7, 81 PD8/LCD0_D12/LVDS0_D3P/DSI_DP3/PD_EINT8, 82 PD9/LCD0_D13/LVDS0_D3N/DSI_DM3/PD_EINT9, 83 PD10/LCD0_D14/LVDS1_D0P/SPI1_CS/PD_EINT1, 84 PD11/LCD0_D15/LVDS1_D0N/SPI1_CLK/PD_EINT, 85 PD12/LCD0_D18/LVDS1_D1P/SPI1_MOSI/PD_EIN, 86 PD13/LCD0_D19/LVDS1_D1N/SPI1_MISO/PD_EIN, 87 PD14/LCD0_D20/LVDS1_D2P/UART3_TX/PD_EINT, 88 PD15/LCD0_D21/LVDS1_D2N/UART3_RX/PD_EINT (power), 89 PD16/LCD0_D22/LVDS1_CKP/PLL_TEST_CKP/UAR, 90 PD17/LCD0_D23/LVDS1_CKN/PLL_TEST_CKN/UAR, 91 PD18/LCD0_CLK/LVDS1_D3P/UART4_TX/PD_EINT, 92 PD19/LCD0_DE/LVDS1_D3N/UART4_RX/PD_EINT1, 93 PD20/LCD0_HSYNC_/PWM2/UART4_RTS/PD_EINT2, 94 PD21/LCD0_VSYNC/PWM3/UART4_CTS/PD_EINT21, 95 PD23/PWM0/TWI0_SDA/PD_EINT23, 96 PC12/NAND_DQS/SPI0_CLK/PC_EINT12 (io), 97 PC7/NAND_RB1/SPI0_CS1/PC_EINT7, 98 PC4/NAND_CE0/SPI0_MISO/PC_EINT4, 99 PC3/NAND_CE1/SPI0_CS0/PC_EINT3, 100 PC2/NAND_CLE/SPI0_MOSI/PC_EINT2, 101 USB1-DP, 102 USB1-DM, 103 PH8/DMIC_CLK/SPI2_CS/I2S2_MCLK/I2S2_DIN2, 104 USB0-DP, 105 USB0-DM, 106 VBUS, 107 VBAT, 108 VBAT, 109 TS, 110 PS, 111 PWRON, 112 GND, 113 ACIN2, 114 ACIN1, 115 PE9/BIST_RESULT3/I2S2_DIN0/PE_EINT9, 116 PE8/BIST_RESULT2/I2S2_DOUT0/PE_EINT8, 117 PE7/CSI_SM_VS/BIST_RESULT1/I2S2_LRCK/TCO, 118 PE6/BIST_RESULT0/I2S2_BCLK/PE_EINT6, 119 PE4/TWI3_SDA/PE_EINT4, 120 PE3/TWI3_SCK/PE_EINT3, 121 GND, 122 MCSIA_D3N, 123 MCSIA_D3P (power), 124 MCSIA_D2N, 125 MCSIA_D2P, 126 MCSIA_D1N, 127 MCSIA_D1P, 128 MCSIA_D0N (power), 129 MCSIA_D0P (power), 130 MCSIA_CLKN, 131 MCSIA_CLKP, 132 MCSIB_D1N, 133 MCSIB_D1P, 134 MCSIB_D0N, 135 MCSIB_D0P, 136 MCSIB_CLKN, 137 MCSIB_CLKP, 138 PE5/MIPI_MCLK1/PLL_LOCK_DBG/I2S2_MCLK/LE, 139 PE0/MIPI_MCLK0/PE_EINT0, 140 PE1/TWI2_SCK/PE_EINT1, 141 PE2/TWI2_SDA/PE_EINT2, 142 AFVCC-CSI, 143 DVDD-CSI, 144 AVDD-CSI

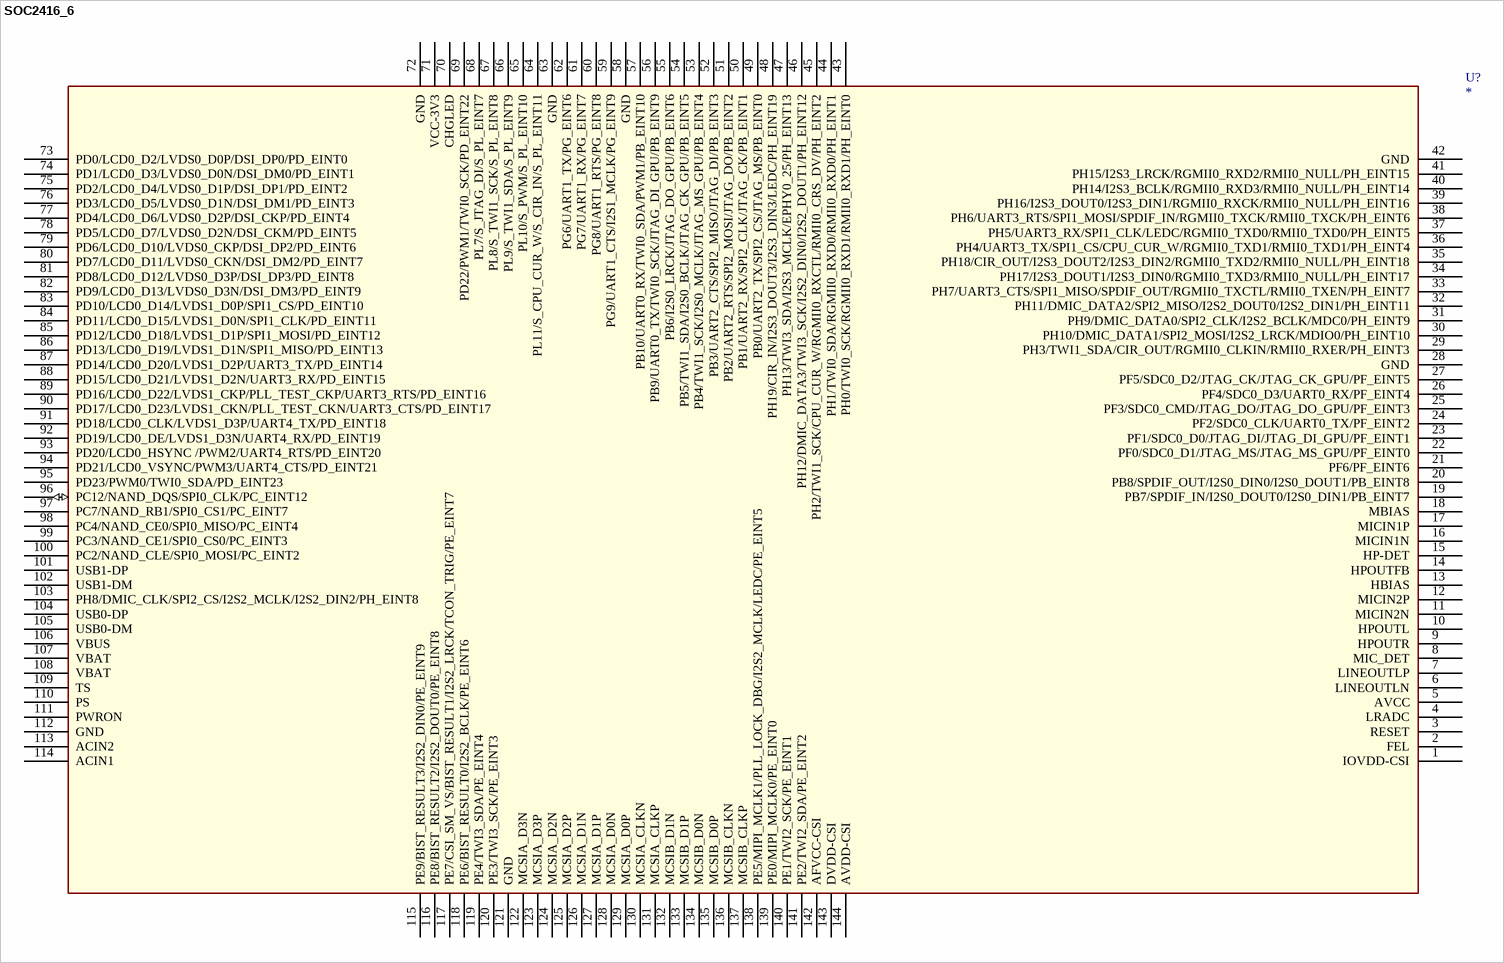
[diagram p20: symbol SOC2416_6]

## SOC2416_6
designator U?
footprint SOC4X4_1MM
pins: 1 IOVDD-CSI, 2 FEL, 3 RESET, 4 LRADC, 5 AVCC, 6 LINEOUTLN, 7 LINEOUTLP, 8 MIC_DET, 9 HPOUTR, 10 HPOUTL, 11 MICIN2N, 12 MICIN2P, 13 HBIAS, 14 HPOUTFB, 15 HP-DET, 16 MICIN1N, 17 MICIN1P, 18 MBIAS, 19 PB7/SPDIF_IN/I2S0_DOUT0/I2S0_DIN1/PB_EINT7, 20 PB8/SPDIF_OUT/I2S0_DIN0/I2S0_DOUT1/PB_EINT8, 21 PF6/PF_EINT6, 22 PF0/SDC0_D1/JTAG_MS/JTAG_MS_GPU/PF_EINT0, 23 PF1/SDC0_D0/JTAG_DI/JTAG_DI_GPU/PF_EINT1, 24 PF2/SDC0_CLK/UART0_TX/PF_EINT2, 25 PF3/SDC0_CMD/JTAG_DO/JTAG_DO_GPU/PF_EINT3, 26 PF4/SDC0_D3/UART0_RX/PF_EINT4, 27 PF5/SDC0_D2/JTAG_CK/JTAG_CK_GPU/PF_EINT5, 28 GND, 29 PH3/TWI1_SDA/CIR_OUT/RGMII0_CLKIN/RMII0_RXER/PH_EINT3, 30 PH10/DMIC_DATA1/SPI2_MOSI/I2S2_LRCK/MDIO0/PH_EINT10, 31 PH9/DMIC_DATA0/SPI2_CLK/I2S2_BCLK/MDC0/PH_EINT9, 32 PH11/DMIC_DATA2/SPI2_MISO/I2S2_DOUT0/I2S2_DIN1/PH_EINT11, 33 PH7/UART3_CTS/SPI1_MISO/SPDIF_OUT/RGMII0_TXCTL/RMII0_TXEN/PH_EINT7, 34 PH17/I2S3_DOUT1/I2S3_DIN0/RGMII0_TXD3/RMII0_NULL/PH_EINT17, 35 PH18/CIR_OUT/I2S3_DOUT2/I2S3_DIN2/RGMII0_TXD2/RMII0_NULL/PH_EINT18, 36 PH4/UART3_TX/SPI1_CS/CPU_CUR_W/RGMII0_TXD1/RMII0_TXD1/PH_EINT4, 37 PH5/UART3_RX/SPI1_CLK/LEDC/RGMII0_TXD0/RMII0_TXD0/PH_EINT5, 38 PH6/UART3_RTS/SPI1_MOSI/SPDIF_IN/RGMII0_TXCK/RMII0_TXCK/PH_EINT6, 39 PH16/I2S3_DOUT0/I2S3_DIN1/RGMII0_RXCK/RMII0_NULL/PH_EINT16, 40 PH14/I2S3_BCLK/RGMII0_RXD3/RMII0_NULL/PH_EINT14, 41 PH15/I2S3_LRCK/RGMII0_RXD2/RMII0_NULL/PH_EINT15, 42 GND, 43 PH0/TWI0_SCK/RGMII0_RXD1/RMII0_RXD1/PH_EINT0, 44 PH1/TWI0_SDA/RGMII0_RXD0/RMII0_RXD0/PH_EINT1, 45 PH2/TWI1_SCK/CPU_CUR_W/RGMII0_RXCTL/RMII0_CRS_DV/PH_EINT2, 46 PH12/DMIC_DATA3/TWI3_SCK/I2S2_DIN0/I2S2_DOUT1/PH_EINT12, 47 PH13/TWI3_SDA/I2S3_MCLK/EPHY0_25/PH_EINT13, 48 PH19/CIR_IN/I2S3_DOUT3/I2S3_DIN3/LEDC/PH_EINT19, 49 PB0/UART2_TX/SPI2_CS/JTAG_MS/PB_EINT0, 50 PB1/UART2_RX/SPI2_CLK/JTAG_CK/PB_EINT1, 51 PB2/UART2_RTS/SPI2_MOSI/JTAG_DO/PB_EINT2, 52 PB3/UART2_CTS/SPI2_MISO/JTAG_DI/PB_EINT3, 53 PB4/TWI1_SCK/I2S0_MCLK/JTAG_MS_GPU/PB_EINT4, 54 PB5/TWI1_SDA/I2S0_BCLK/JTAG_CK_GPU/PB_EINT5, 55 PB6/I2S0_LRCK/JTAG_DO_GPU/PB_EINT6, 56 PB9/UART0_TX/TWI0_SCK/JTAG_DI_GPU/PB_EINT9, 57 PB10/UART0_RX/TWI0_SDA/PWM1/PB_EINT10 (power), 58 GND, 59 PG9/UART1_CTS/I2S1_MCLK/PG_EINT9, 60 PG8/UART1_RTS/PG_EINT8, 61 PG7/UART1_RX/PG_EINT7, 62 PG6/UART1_TX/PG_EINT6, 63 GND, 64 PL11/S_CPU_CUR_W/S_CIR_IN/S_PL_EINT11, 65 PL10/S_PWM/S_PL_EINT10, 66 PL9/S_TWI1_SDA/S_PL_EINT9, 67 PL8/S_TWI1_SCK/S_PL_EINT8, 68 PL7/S_JTAG_DI/S_PL_EINT7, 69 PD22/PWM1/TWI0_SCK/PD_EINT22, 70 CHGLED, 71 VCC-3V3, 72 GND, 73 PD0/LCD0_D2/LVDS0_D0P/DSI_DP0/PD_EINT0, 74 PD1/LCD0_D3/LVDS0_D0N/DSI_DM0/PD_EINT1, 75 PD2/LCD0_D4/LVDS0_D1P/DSI_DP1/PD_EINT2, 76 PD3/LCD0_D5/LVDS0_D1N/DSI_DM1/PD_EINT3, 77 PD4/LCD0_D6/LVDS0_D2P/DSI_CKP/PD_EINT4, 78 PD5/LCD0_D7/LVDS0_D2N/DSI_CKM/PD_EINT5, 79 PD6/LCD0_D10/LVDS0_CKP/DSI_DP2/PD_EINT6, 80 PD7/LCD0_D11/LVDS0_CKN/DSI_DM2/PD_EINT7, 81 PD8/LCD0_D12/LVDS0_D3P/DSI_DP3/PD_EINT8, 82 PD9/LCD0_D13/LVDS0_D3N/DSI_DM3/PD_EINT9, 83 PD10/LCD0_D14/LVDS1_D0P/SPI1_CS/PD_EINT10, 84 PD11/LCD0_D15/LVDS1_D0N/SPI1_CLK/PD_EINT11, 85 PD12/LCD0_D18/LVDS1_D1P/SPI1_MOSI/PD_EINT12, 86 PD13/LCD0_D19/LVDS1_D1N/SPI1_MISO/PD_EINT13, 87 PD14/LCD0_D20/LVDS1_D2P/UART3_TX/PD_EINT14, 88 PD15/LCD0_D21/LVDS1_D2N/UART3_RX/PD_EINT15 (power), 89 PD16/LCD0_D22/LVDS1_CKP/PLL_TEST_CKP/UART3_RTS/PD_EINT16, 90 PD17/LCD0_D23/LVDS1_CKN/PLL_TEST_CKN/UART3_CTS/PD_EINT17, 91 PD18/LCD0_CLK/LVDS1_D3P/UART4_TX/PD_EINT18, 92 PD19/LCD0_DE/LVDS1_D3N/UART4_RX/PD_EINT19, 93 PD20/LCD0_HSYNC /PWM2/UART4_RTS/PD_EINT20, 94 PD21/LCD0_VSYNC/PWM3/UART4_CTS/PD_EINT21, 95 PD23/PWM0/TWI0_SDA/PD_EINT23, 96 PC12/NAND_DQS/SPI0_CLK/PC_EINT12 (io), 97 PC7/NAND_RB1/SPI0_CS1/PC_EINT7, 98 PC4/NAND_CE0/SPI0_MISO/PC_EINT4, 99 PC3/NAND_CE1/SPI0_CS0/PC_EINT3, 100 PC2/NAND_CLE/SPI0_MOSI/PC_EINT2, 101 USB1-DP, 102 USB1-DM, 103 PH8/DMIC_CLK/SPI2_CS/I2S2_MCLK/I2S2_DIN2/PH_EINT8, 104 USB0-DP, 105 USB0-DM, 106 VBUS, 107 VBAT, 108 VBAT, 109 TS, 110 PS, 111 PWRON, 112 GND, 113 ACIN2, 114 ACIN1, 115 PE9/BIST_RESULT3/I2S2_DIN0/PE_EINT9, 116 PE8/BIST_RESULT2/I2S2_DOUT0/PE_EINT8, 117 PE7/CSI_SM_VS/BIST_RESULT1/I2S2_LRCK/TCON_TRIG/PE_EINT7, 118 PE6/BIST_RESULT0/I2S2_BCLK/PE_EINT6, 119 PE4/TWI3_SDA/PE_EINT4, 120 PE3/TWI3_SCK/PE_EINT3, 121 GND, 122 MCSIA_D3N, 123 MCSIA_D3P (power), 124 MCSIA_D2N, 125 MCSIA_D2P, 126 MCSIA_D1N, 127 MCSIA_D1P, 128 MCSIA_D0N (power), 129 MCSIA_D0P (power), 130 MCSIA_CLKN, 131 MCSIA_CLKP, 132 MCSIB_D1N, 133 MCSIB_D1P, 134 MCSIB_D0N, 135 MCSIB_D0P, 136 MCSIB_CLKN, 137 MCSIB_CLKP, 138 PE5/MIPI_MCLK1/PLL_LOCK_DBG/I2S2_MCLK/LEDC/PE_EINT5, 139 PE0/MIPI_MCLK0/PE_EINT0, 140 PE1/TWI2_SCK/PE_EINT1, 141 PE2/TWI2_SDA/PE_EINT2, 142 AFVCC-CSI, 143 DVDD-CSI, 144 AVDD-CSI

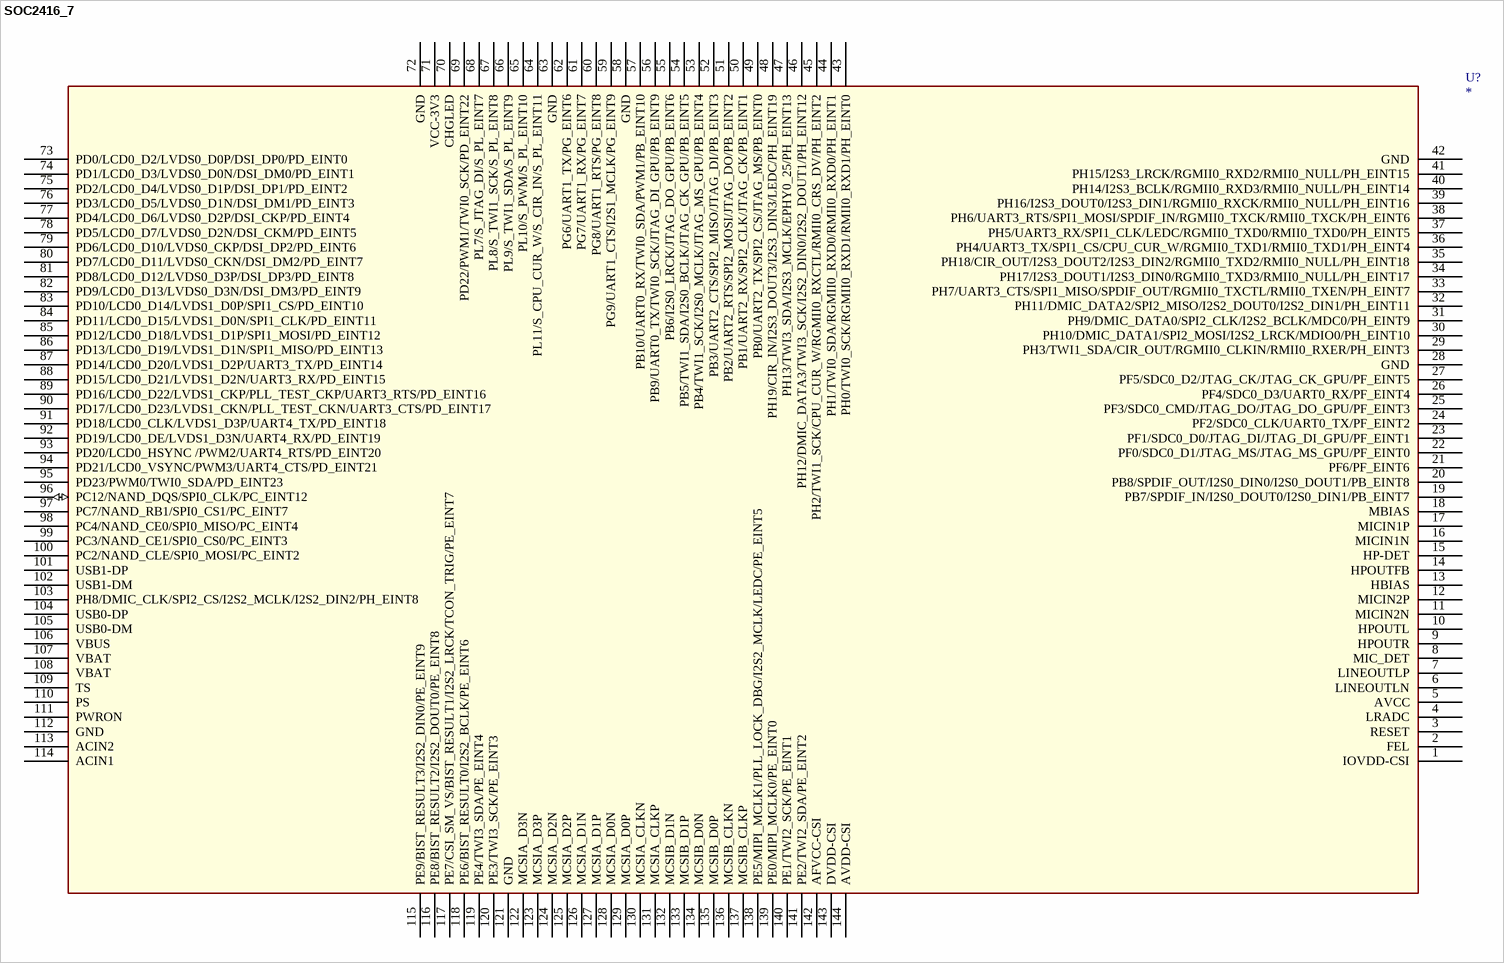
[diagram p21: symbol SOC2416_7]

## SOC2416_7
designator U?
footprint SOC4X4_1MM
pins: 1 IOVDD-CSI, 2 FEL, 3 RESET, 4 LRADC, 5 AVCC, 6 LINEOUTLN, 7 LINEOUTLP, 8 MIC_DET, 9 HPOUTR, 10 HPOUTL, 11 MICIN2N, 12 MICIN2P, 13 HBIAS, 14 HPOUTFB, 15 HP-DET, 16 MICIN1N, 17 MICIN1P, 18 MBIAS, 19 PB7/SPDIF_IN/I2S0_DOUT0/I2S0_DIN1/PB_EINT7, 20 PB8/SPDIF_OUT/I2S0_DIN0/I2S0_DOUT1/PB_EINT8, 21 PF6/PF_EINT6, 22 PF0/SDC0_D1/JTAG_MS/JTAG_MS_GPU/PF_EINT0, 23 PF1/SDC0_D0/JTAG_DI/JTAG_DI_GPU/PF_EINT1, 24 PF2/SDC0_CLK/UART0_TX/PF_EINT2, 25 PF3/SDC0_CMD/JTAG_DO/JTAG_DO_GPU/PF_EINT3, 26 PF4/SDC0_D3/UART0_RX/PF_EINT4, 27 PF5/SDC0_D2/JTAG_CK/JTAG_CK_GPU/PF_EINT5, 28 GND, 29 PH3/TWI1_SDA/CIR_OUT/RGMII0_CLKIN/RMII0_RXER/PH_EINT3, 30 PH10/DMIC_DATA1/SPI2_MOSI/I2S2_LRCK/MDIO0/PH_EINT10, 31 PH9/DMIC_DATA0/SPI2_CLK/I2S2_BCLK/MDC0/PH_EINT9, 32 PH11/DMIC_DATA2/SPI2_MISO/I2S2_DOUT0/I2S2_DIN1/PH_EINT11, 33 PH7/UART3_CTS/SPI1_MISO/SPDIF_OUT/RGMII0_TXCTL/RMII0_TXEN/PH_EINT7, 34 PH17/I2S3_DOUT1/I2S3_DIN0/RGMII0_TXD3/RMII0_NULL/PH_EINT17, 35 PH18/CIR_OUT/I2S3_DOUT2/I2S3_DIN2/RGMII0_TXD2/RMII0_NULL/PH_EINT18, 36 PH4/UART3_TX/SPI1_CS/CPU_CUR_W/RGMII0_TXD1/RMII0_TXD1/PH_EINT4, 37 PH5/UART3_RX/SPI1_CLK/LEDC/RGMII0_TXD0/RMII0_TXD0/PH_EINT5, 38 PH6/UART3_RTS/SPI1_MOSI/SPDIF_IN/RGMII0_TXCK/RMII0_TXCK/PH_EINT6, 39 PH16/I2S3_DOUT0/I2S3_DIN1/RGMII0_RXCK/RMII0_NULL/PH_EINT16, 40 PH14/I2S3_BCLK/RGMII0_RXD3/RMII0_NULL/PH_EINT14, 41 PH15/I2S3_LRCK/RGMII0_RXD2/RMII0_NULL/PH_EINT15, 42 GND, 43 PH0/TWI0_SCK/RGMII0_RXD1/RMII0_RXD1/PH_EINT0, 44 PH1/TWI0_SDA/RGMII0_RXD0/RMII0_RXD0/PH_EINT1, 45 PH2/TWI1_SCK/CPU_CUR_W/RGMII0_RXCTL/RMII0_CRS_DV/PH_EINT2, 46 PH12/DMIC_DATA3/TWI3_SCK/I2S2_DIN0/I2S2_DOUT1/PH_EINT12, 47 PH13/TWI3_SDA/I2S3_MCLK/EPHY0_25/PH_EINT13, 48 PH19/CIR_IN/I2S3_DOUT3/I2S3_DIN3/LEDC/PH_EINT19, 49 PB0/UART2_TX/SPI2_CS/JTAG_MS/PB_EINT0, 50 PB1/UART2_RX/SPI2_CLK/JTAG_CK/PB_EINT1, 51 PB2/UART2_RTS/SPI2_MOSI/JTAG_DO/PB_EINT2, 52 PB3/UART2_CTS/SPI2_MISO/JTAG_DI/PB_EINT3, 53 PB4/TWI1_SCK/I2S0_MCLK/JTAG_MS_GPU/PB_EINT4, 54 PB5/TWI1_SDA/I2S0_BCLK/JTAG_CK_GPU/PB_EINT5, 55 PB6/I2S0_LRCK/JTAG_DO_GPU/PB_EINT6, 56 PB9/UART0_TX/TWI0_SCK/JTAG_DI_GPU/PB_EINT9, 57 PB10/UART0_RX/TWI0_SDA/PWM1/PB_EINT10 (power), 58 GND, 59 PG9/UART1_CTS/I2S1_MCLK/PG_EINT9, 60 PG8/UART1_RTS/PG_EINT8, 61 PG7/UART1_RX/PG_EINT7, 62 PG6/UART1_TX/PG_EINT6, 63 GND, 64 PL11/S_CPU_CUR_W/S_CIR_IN/S_PL_EINT11, 65 PL10/S_PWM/S_PL_EINT10, 66 PL9/S_TWI1_SDA/S_PL_EINT9, 67 PL8/S_TWI1_SCK/S_PL_EINT8, 68 PL7/S_JTAG_DI/S_PL_EINT7, 69 PD22/PWM1/TWI0_SCK/PD_EINT22, 70 CHGLED, 71 VCC-3V3, 72 GND, 73 PD0/LCD0_D2/LVDS0_D0P/DSI_DP0/PD_EINT0, 74 PD1/LCD0_D3/LVDS0_D0N/DSI_DM0/PD_EINT1, 75 PD2/LCD0_D4/LVDS0_D1P/DSI_DP1/PD_EINT2, 76 PD3/LCD0_D5/LVDS0_D1N/DSI_DM1/PD_EINT3, 77 PD4/LCD0_D6/LVDS0_D2P/DSI_CKP/PD_EINT4, 78 PD5/LCD0_D7/LVDS0_D2N/DSI_CKM/PD_EINT5, 79 PD6/LCD0_D10/LVDS0_CKP/DSI_DP2/PD_EINT6, 80 PD7/LCD0_D11/LVDS0_CKN/DSI_DM2/PD_EINT7, 81 PD8/LCD0_D12/LVDS0_D3P/DSI_DP3/PD_EINT8, 82 PD9/LCD0_D13/LVDS0_D3N/DSI_DM3/PD_EINT9, 83 PD10/LCD0_D14/LVDS1_D0P/SPI1_CS/PD_EINT10, 84 PD11/LCD0_D15/LVDS1_D0N/SPI1_CLK/PD_EINT11, 85 PD12/LCD0_D18/LVDS1_D1P/SPI1_MOSI/PD_EINT12, 86 PD13/LCD0_D19/LVDS1_D1N/SPI1_MISO/PD_EINT13, 87 PD14/LCD0_D20/LVDS1_D2P/UART3_TX/PD_EINT14, 88 PD15/LCD0_D21/LVDS1_D2N/UART3_RX/PD_EINT15 (power), 89 PD16/LCD0_D22/LVDS1_CKP/PLL_TEST_CKP/UART3_RTS/PD_EINT16, 90 PD17/LCD0_D23/LVDS1_CKN/PLL_TEST_CKN/UART3_CTS/PD_EINT17, 91 PD18/LCD0_CLK/LVDS1_D3P/UART4_TX/PD_EINT18, 92 PD19/LCD0_DE/LVDS1_D3N/UART4_RX/PD_EINT19, 93 PD20/LCD0_HSYNC /PWM2/UART4_RTS/PD_EINT20, 94 PD21/LCD0_VSYNC/PWM3/UART4_CTS/PD_EINT21, 95 PD23/PWM0/TWI0_SDA/PD_EINT23, 96 PC12/NAND_DQS/SPI0_CLK/PC_EINT12 (io), 97 PC7/NAND_RB1/SPI0_CS1/PC_EINT7, 98 PC4/NAND_CE0/SPI0_MISO/PC_EINT4, 99 PC3/NAND_CE1/SPI0_CS0/PC_EINT3, 100 PC2/NAND_CLE/SPI0_MOSI/PC_EINT2, 101 USB1-DP, 102 USB1-DM, 103 PH8/DMIC_CLK/SPI2_CS/I2S2_MCLK/I2S2_DIN2/PH_EINT8, 104 USB0-DP, 105 USB0-DM, 106 VBUS, 107 VBAT, 108 VBAT, 109 TS, 110 PS, 111 PWRON, 112 GND, 113 ACIN2, 114 ACIN1, 115 PE9/BIST_RESULT3/I2S2_DIN0/PE_EINT9, 116 PE8/BIST_RESULT2/I2S2_DOUT0/PE_EINT8, 117 PE7/CSI_SM_VS/BIST_RESULT1/I2S2_LRCK/TCON_TRIG/PE_EINT7, 118 PE6/BIST_RESULT0/I2S2_BCLK/PE_EINT6, 119 PE4/TWI3_SDA/PE_EINT4, 120 PE3/TWI3_SCK/PE_EINT3, 121 GND, 122 MCSIA_D3N, 123 MCSIA_D3P, 124 MCSIA_D2N, 125 MCSIA_D2P, 126 MCSIA_D1N, 127 MCSIA_D1P, 128 MCSIA_D0N, 129 MCSIA_D0P, 130 MCSIA_CLKN, 131 MCSIA_CLKP, 132 MCSIB_D1N, 133 MCSIB_D1P, 134 MCSIB_D0N, 135 MCSIB_D0P, 136 MCSIB_CLKN, 137 MCSIB_CLKP, 138 PE5/MIPI_MCLK1/PLL_LOCK_DBG/I2S2_MCLK/LEDC/PE_EINT5, 139 PE0/MIPI_MCLK0/PE_EINT0, 140 PE1/TWI2_SCK/PE_EINT1, 141 PE2/TWI2_SDA/PE_EINT2, 142 AFVCC-CSI, 143 DVDD-CSI, 144 AVDD-CSI

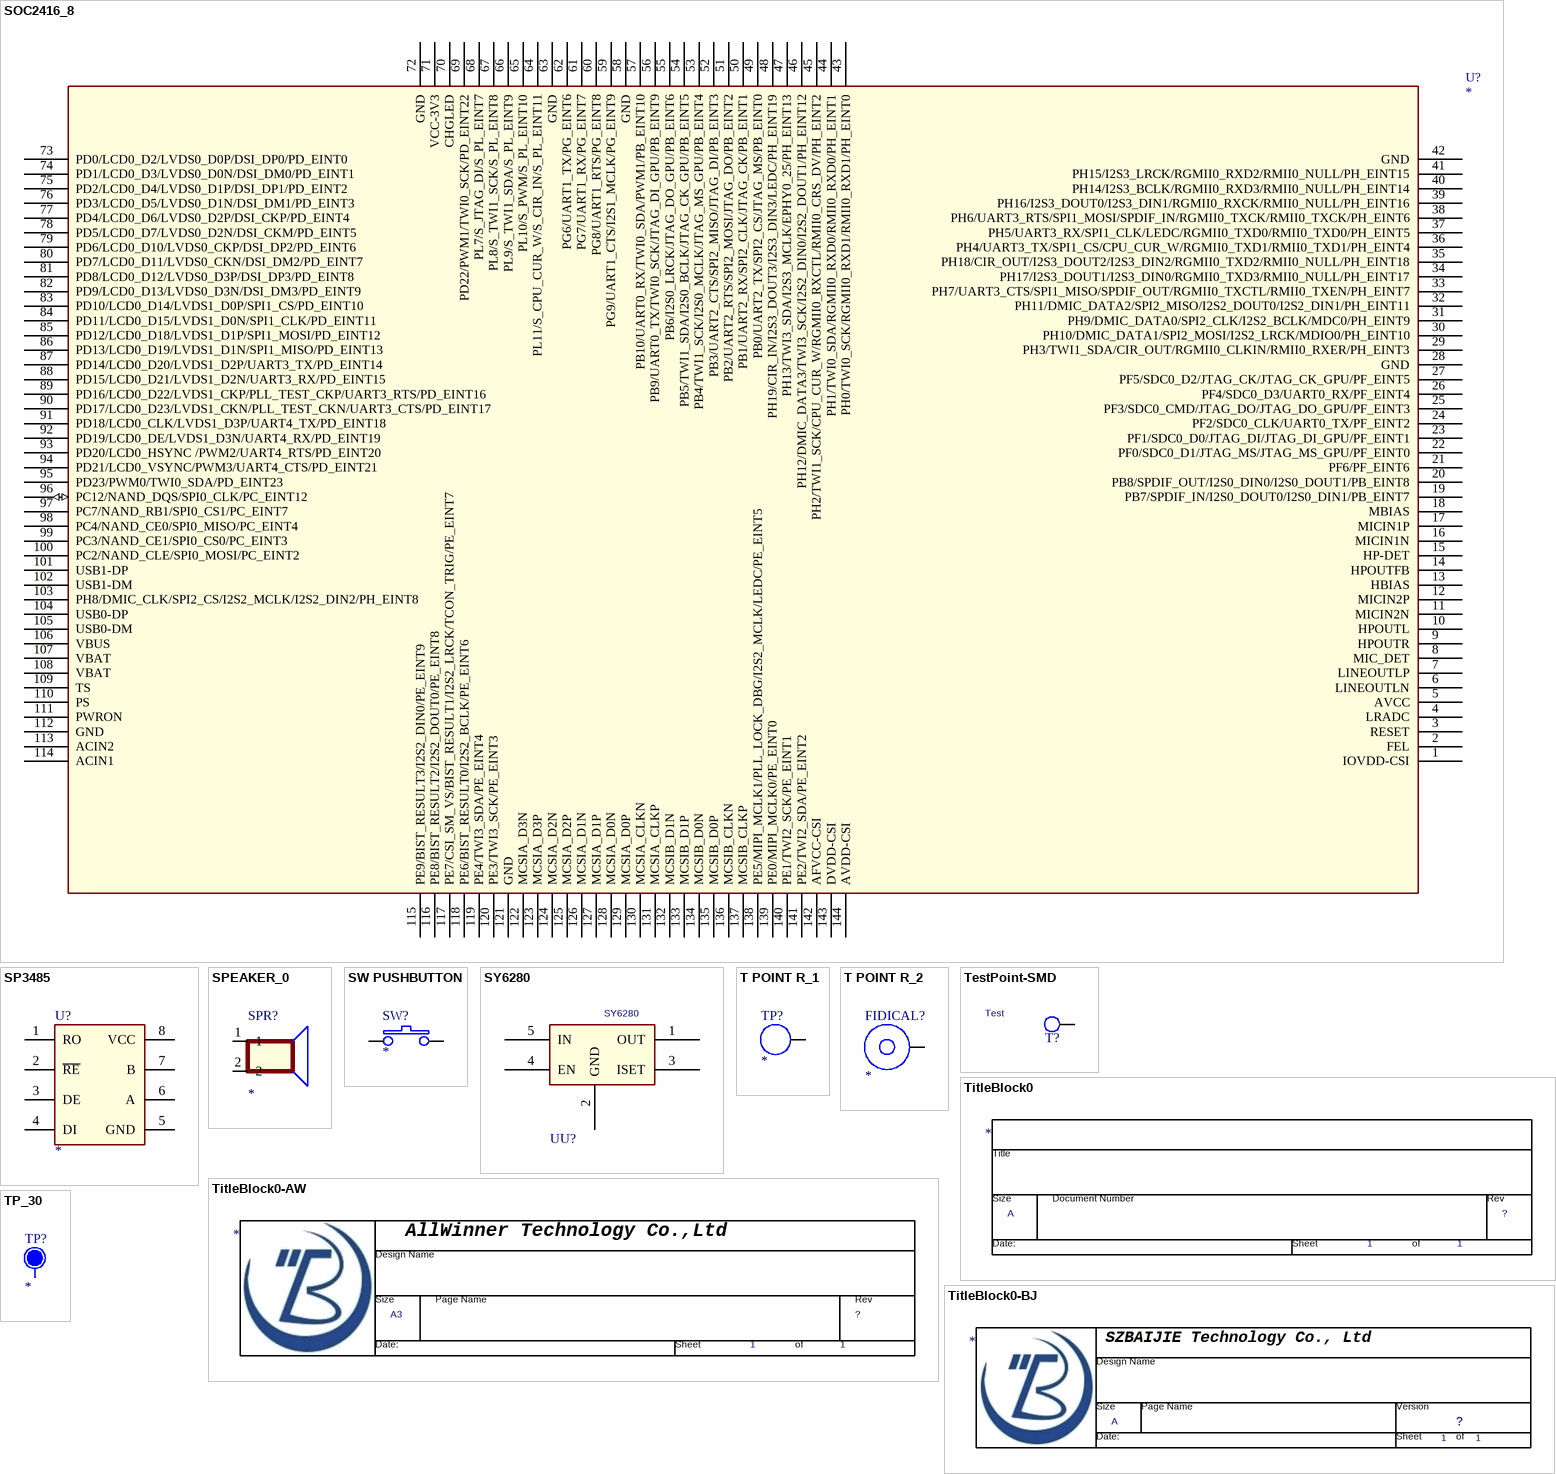
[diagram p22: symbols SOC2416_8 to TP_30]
